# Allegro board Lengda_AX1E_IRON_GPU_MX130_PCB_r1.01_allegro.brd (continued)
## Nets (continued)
GND: C1.2 C2.2 C3.2 C4.2 C5.2 C6.2 C7.2 C8.2 C9.2 C10.2 C11.2 C12.2 C13.2 C14.2 C15.2 C16.2 C17.2 C18.2 C20.1 C21.1 C22.1 C23.1 C24.1 C275.2 C276.2 C298.2 C310.2 C322.2 C326.2 C327.2 C338.2 C342.2 C344.2 C370.2 C471.2 C472.2 C473.2 C474.2 C475.2 C476.2 C536.2 C537.2 C539.2 C540.2 C541.2 C542.2 C543.2 C553.2 C554.2 C555.2 C556.2 C557.2 C558.2 C559.2 C560.2 C561.2 C562.2 C567.2 C568.2 C569.2 C570.2 C571.2 C572.2 C573.2 C574.2 C575.2 C576.2 C577.2 C578.2 C579.2 C580.2 C581.2 C582.2 C583.2 C584.2 C585.2 C586.2 C587.2 C588.2 C596.2 C597.2 C598.2 C599.2 C600.2 C602.2 C603.2 C604.2 C605.2 C606.2 C607.2 C619.2 C620.2 C621.2 C622.2 C623.1 C624.2 C625.2 C628.2 C629.2 C630.1 C631.2 C632.2 C633.2 C634.2 C635.2 C636.2 C637.2 C638.2 C647.2 C670.2 C672.1 C681.2 C682.2 C683.2 C684.2 C691.2 C692.2 C707.2 C710.2 C715.2 C726.2 C729.2 C739.2 C741.2 C742.2 C743.2 C744.2 C745.2 C748.1 C749.2 C758.2 C759.2 C761.2 C764.2 C765.2 C766.2 C769.2 C783.2 C789.2 C804.2 C805.2 C809.2 C810.2 C811.2 C812.2 C813.2 C814.2 C815.2 C816.2 C817.2 C818.2 C819.2 C820.2 C821.2 C822.2 C823.2 C824.2 C825.2 C826.2 C827.2 C828.2 C829.2 C830.2 C831.2 C832.2 C833.2 C834.2 C835.2 C836.2 C837.2 C838.2 C839.2 C840.2 C841.2 C842.2 C843.2 C844.2 C845.2 C846.2 C847.2 C848.2 C849.2 C850.2 C851.2 C852.2 C853.2 C854.2 C855.2 C856.2 C857.2 C858.2 C859.2 C860.2 C861.2 C862.2 C863.2 C864.2 C865.2 C866.2 C867.1 C868.2 C869.2 C870.2 C871.2 C872.2 C873.2 C874.2 C875.2 C876.2 C878.1 C879.1 C881.2 C882.2 C883.2 C884.2 C885.2 C886.2 C887.2 C888.2 C891.2 C896.2 C898.2 C899.2 C900.1 C901.2 C903.2 C904.2 C909.2 C910.1 C911.2 C912.2 C913.1 C914.1 C915.1 C916.1 C917.2 C918.2 C920.2 C921.2 C922.2 C923.2 C924.2 C925.2 C927.2 C928.2 C929.2 C930.2 C931.2 C932.2 C933.2 CP1.2 CP3.2 CP4.2 CP10.2 CP11.2 CP12.2 CP13.2 GC1.2 GC2.1 GC3.1 GC315.1 GC316.2 GC317.1 GCN1.9(GND1) GCN1.15(GND2) GCN1.21(GND3) GCN1.27(GND4) GCN1.29(GND5) GCN1.34(GND10) GCN1.35(GND6) GCN1.40(GND11) GCN1.41(RSVD7) GCN1.47(C_DAT) GCN1.50(GND12) GCN2.E1 GCN2.E2 GCN9.4 GCN9.E1 GCN9.E2 GQ2.2(GND) GR9.2 GR13.2 GU1.22(GND/PWM3) GU1.E1(THERM/GND) M1.A1(VSSQ_1) M1.A3(VSSQ_4) M1.A12(VSSQ_2) M1.A14(VSSQ_3) M1.B5(VSS_2) M1.B10(VSS_1) M1.C1(VSSQ_5) M1.C3(VSSQ_9) M1.C4(VSSQ_10) M1.C11(VSSQ_6) M1.C12(VSSQ_7) M1.C13(EDC1_X16) M1.C14(VSSQ_8) M1.D10(VSS_3) M1.E1(VSSQ_11) M1.E3(VSSQ_14) M1.E12(VSSQ_12) M1.E14(VSSQ_13) M1.F5(VSSQ_16) M1.F10(VSSQ_15) M1.G5(VSS_5) M1.G10(VSS_4) M1.H1(VSS_6) M1.H2(VSSQ_18) M1.H13(VSSQ_17) M1.H14(VSS_7) M1.K1(VSS_8) M1.K2(VSSQ_20) M1.K13(VSSQ_19) M1.K14(VSS_9) M1.L5(VSS_11) M1.L10(VSS_10) M1.M5(VSSQ_22) M1.M10(VSSQ_21) M1.N1(VSSQ_23) M1.N3(VSSQ_26) M1.N12(VSSQ_24) M1.N14(VSSQ_25) M1.P10(VSS_12) M1.R1(VSSQ_27) M1.R3(VSSQ_31) M1.R4(VSSQ_32) M1.R11(VSSQ_28) M1.R12(VSSQ_29) M1.R14(VSSQ_30) M1.T5(VSS_14) M1.T10(VSS_13) M1.V1(VSSQ_33) M1.V3(VSSQ_36) M1.V12(VSSQ_34) M1.V14(VSSQ_35) M2.A1(VSSQ_1) M2.A3(VSSQ_4) M2.A12(VSSQ_2) M2.A14(VSSQ_3) M2.B5(VSS_2) M2.B10(VSS_1) M2.C1(VSSQ_5) M2.C3(VSSQ_9) M2.C4(VSSQ_10) M2.C11(VSSQ_6) M2.C12(VSSQ_7) M2.C13(EDC2_X16) M2.C14(VSSQ_8) M2.D10(VSS_3) M2.E1(VSSQ_11) M2.E3(VSSQ_14) M2.E12(VSSQ_12) M2.E14(VSSQ_13) M2.F5(VSSQ_16) M2.F10(VSSQ_15) M2.G5(VSS_5) M2.G10(VSS_4) M2.H1(VSS_6) M2.H2(VSSQ_18) M2.H13(VSSQ_17) M2.H14(VSS_7) M2.K1(VSS_8) M2.K2(VSSQ_20) M2.K13(VSSQ_19) M2.K14(VSS_9) M2.L5(VSS_11) M2.L10(VSS_10) M2.M5(VSSQ_22) M2.M10(VSSQ_21) M2.N1(VSSQ_23) M2.N3(VSSQ_26) M2.N12(VSSQ_24) M2.N14(VSSQ_25) M2.P10(VSS_12) M2.R1(VSSQ_27) M2.R3(VSSQ_31) M2.R4(VSSQ_32) M2.R11(VSSQ_28) M2.R12(VSSQ_29) M2.R14(VSSQ_30) M2.T5(VSS_14) M2.T10(VSS_13) M2.V1(VSSQ_33) M2.V3(VSSQ_36) M2.V12(VSSQ_34) M2.V14(VSSQ_35) M3.A1(VSSQ_1) M3.A3(VSSQ_4) M3.A12(VSSQ_2) M3.A14(VSSQ_3) M3.B5(VSS_2) M3.B10(VSS_1) M3.C1(VSSQ_5) M3.C3(VSSQ_9) M3.C4(VSSQ_10) M3.C11(VSSQ_6) M3.C12(VSSQ_7) M3.C13(EDC2_X16) M3.C14(VSSQ_8) M3.D10(VSS_3) M3.E1(VSSQ_11) M3.E3(VSSQ_14) M3.E12(VSSQ_12) M3.E14(VSSQ_13) M3.F5(VSSQ_16) M3.F10(VSSQ_15) M3.G5(VSS_5) M3.G10(VSS_4) M3.H1(VSS_6) M3.H2(VSSQ_18) M3.H13(VSSQ_17) M3.H14(VSS_7) M3.K1(VSS_8) M3.K2(VSSQ_20) M3.K13(VSSQ_19) M3.K14(VSS_9) M3.L5(VSS_11) M3.L10(VSS_10) M3.M5(VSSQ_22) M3.M10(VSSQ_21) M3.N1(VSSQ_23) M3.N3(VSSQ_26) M3.N12(VSSQ_24) M3.N14(VSSQ_25) M3.P10(VSS_12) M3.R1(VSSQ_27) M3.R3(VSSQ_31) M3.R4(VSSQ_32) M3.R11(VSSQ_28) M3.R12(VSSQ_29) M3.R14(VSSQ_30) M3.T5(VSS_14) M3.T10(VSS_13) M3.V1(VSSQ_33) M3.V3(VSSQ_36) M3.V12(VSSQ_34) M3.V14(VSSQ_35) M4.A1(VSSQ_1) M4.A3(VSSQ_4) M4.A12(VSSQ_2) M4.A14(VSSQ_3) M4.B5(VSS_2) M4.B10(VSS_1) M4.C1(VSSQ_5) M4.C3(VSSQ_9) M4.C4(VSSQ_10) M4.C11(VSSQ_6) M4.C12(VSSQ_7) M4.C13(EDC1_X16) M4.C14(VSSQ_8) M4.D10(VSS_3) M4.E1(VSSQ_11) M4.E3(VSSQ_14) M4.E12(VSSQ_12) M4.E14(VSSQ_13) M4.F5(VSSQ_16) M4.F10(VSSQ_15) M4.G5(VSS_5) M4.G10(VSS_4) M4.H1(VSS_6) M4.H2(VSSQ_18) M4.H13(VSSQ_17) M4.H14(VSS_7) M4.K1(VSS_8) M4.K2(VSSQ_20) M4.K13(VSSQ_19) M4.K14(VSS_9) M4.L5(VSS_11) M4.L10(VSS_10) M4.M5(VSSQ_22) M4.M10(VSSQ_21) M4.N1(VSSQ_23) M4.N3(VSSQ_26) M4.N12(VSSQ_24) M4.N14(VSSQ_25) M4.P10(VSS_12) M4.R1(VSSQ_27) M4.R3(VSSQ_31) M4.R4(VSSQ_32) M4.R11(VSSQ_28) M4.R12(VSSQ_29) M4.R14(VSSQ_30) M4.T5(VSS_14) M4.T10(VSS_13) M4.V1(VSSQ_33) M4.V3(VSSQ_36) M4.V12(VSSQ_34) M4.V14(VSSQ_35) MH1.1 MH2.1 MH3.1 MH4.1 MH5.1 MH6.1 MH7.1 MH8.1 MH9.1 MH10.1 MH11.1 PCP3.2 Q2.2(S) Q4.2(S) Q7.2(S) Q25.2(S) Q30.2(S) Q38.1(S1) Q38.2(S2) Q38.3(S3) Q39.1(S1) Q39.2(S2) Q39.3(S3) Q41.1(S1) Q41.2(S2) Q41.3(S3) Q42.1(S1) Q42.2(S2) Q42.3(S3) Q54.1(S1) Q54.2(S2) Q54.3(S3) Q55.2(S) Q70.2(S) Q71.2(S) Q72.2(S) Q75.2(S) Q76.2(S) R4.1 R5.1 R7.1 R9.1 R10.1 R15.2 R18.1 R19.1 R23.1 R32.2 R40.2 R44.2 R171.1 R180.1 R181.1 R187.1 R198.1 R240.1 R241.1 R247.1 R248.1 R391.1 R392.2 R528.1 R532.1 R533.1 R556.1 R566.1 R570.1 R587.1 R595.1 R596.1 R597.1 R604.1 R605.2 R606.2 R648.1 R650.2 R659.2 R661.1 R664.2 R665.2 R688.2 R699.2 R703.2 R738.2 R741.2 R744.1 R748.2 R1722.1 U1.1(GND) U2.5(GND) U3.A2(GND_001) U3.A26(GND_002) U3.AA7(GND_F) U3.AB7(GND_H) U3.AB11(GND_003) U3.AB14(GND_004) U3.AB17(GND_005) U3.AB20(GND_006) U3.AB24(GND_007) U3.AC2(GND_008) U3.AC5(GND_011) U3.AC8(GND_012) U3.AC22(GND_009) U3.AC26(GND_010) U3.AD12(GND_013) U3.AD13(GND_014) U3.AD15(GND_015) U3.AD16(GND_016) U3.AD18(GND_017) U3.AD19(GND_018) U3.AD21(GND_019) U3.AD22(GND_020) U3.AE11(GND_021) U3.AE14(GND_022) U3.AE17(GND_023) U3.AE20(GND_024) U3.AF1(GND_025) U3.AF5(GND_031) U3.AF8(GND_032) U3.AF11(GND_026) U3.AF14(GND_027) U3.AF17(GND_028) U3.AF20(GND_029) U3.AF23(GND_030) U3.AG2(GND_033) U3.AG26(GND_034) U3.B1(GND_035) U3.B5(GND_042) U3.B8(GND_043) U3.B11(GND_036) U3.B14(GND_037) U3.B17(GND_038) U3.B20(GND_039) U3.B23(GND_040) U3.B27(GND_041) U3.E2(GND_047) U3.E5(GND_051) U3.E8(GND_052) U3.E11(GND_044) U3.E14(GND_045) U3.E17(GND_046) U3.E20(GND_048) U3.E22(GND_049) U3.E25(GND_050) U3.H23(GND_054) U3.H25(GND_055) U3.K11(GND_057) U3.K13(GND_058) U3.K15(GND_059) U3.K17(GND_060) U3.L5(GND_069) U3.L10(GND_061) U3.L12(GND_062) U3.L14(GND_063) U3.L16(GND_064) U3.L18(GND_065) U3.L23(GND_067) U3.L25(GND_068) U3.M11(GND_070) U3.M13(GND_071) U3.M15(GND_072) U3.M17(GND_073) U3.N10(GND_074) U3.N12(GND_075) U3.N14(GND_076) U3.N16(GND_077) U3.N18(GND_078) U3.P11(GND_079) U3.P13(GND_080) U3.P15(GND_081) U3.P17(GND_082) U3.P23(GND_084) U3.P26(GND_085) U3.R10(GND_087) U3.R12(GND_088) U3.R14(GND_089) U3.R16(GND_090) U3.R18(GND_091) U3.T11(GND_092) U3.T13(GND_093) U3.T15(GND_094) U3.T17(GND_095) U3.U10(GND_096) U3.U12(GND_097) U3.U14(GND_098) U3.U16(GND_099) U3.U18(GND_100) U3.U23(GND_102) U3.U26(GND_103) U3.V11(GND_105) U3.V13(GND_106) U3.V15(GND_107) U3.V17(GND_108) U3.Y2(GND_109) U3.Y5(GND_112) U3.Y23(GND_110) U3.Y26(GND_111) U4.3(GND) U36.4(GND) U37.7(GND) U37.8(PGND) U37.E1 U38.5(GND) U38.E1 U39.5(GND) U39.E1 U40.4(GND1) U40.5(GND2) U40.E1 U41.3(GND) U43.3(GND) U44.3(GND) U46.3(GND) X6.2 X6.4
GNDS_SENSE: U3.F3(GNDS_SENSE)
VDD_GPU: C911.1 R20.2 R704.1 R705.1 R712.2 R739.1 U38.1(VIN1) U38.2(VIN2)
VDD_GPU_AON: C912.1 Q34.1(G) Q35.1(G) Q36.1(G) R37.1 R41.1 R100.1 R251.2 R257.2 R594.1 R599.1 R601.2 R602.1 R614.1 R615.1 R617.1 R619.2 R622.2 R631.2 R634.1 R635.1 R636.1 R637.1 R638.1 R639.1 R640.1 R641.2 R642.1 R643.1 R645.1 R647.1 R704.2 R705.2 R706.1 R750.1 U38.7(VOUT2) U38.8(VOUT1) U39.1(VIN1) U39.2(VIN2)
VDD_GPU_MAIN: C863.1 FB27.2 FB28.1 Q6.1(G) R2.2 R28.2 R154.2 R250.2 R479.2 R480.2 R481.2 R593.1 R598.1 R706.2 R754.1 U36.8(VCC) U39.7(VOUT2) U39.8(VOUT1)
VDDS_SENSE: U3.F4(VDDS_SENSE)
1.5S_LGATE: R701.1 U37.9(DRVL)
1.5S_UGATE: R698.1 U37.13(DRVH)
+VSYS_DCIN: C739.1 C868.1 C869.1 C870.1 C871.1 C872.1 C873.1 C881.1 C882.1 C883.1 C884.1 C885.1 C886.1 C887.1 C896.1 C898.1 CP12.1 GC1.1 GCN1.10(UIM_DATA) GCN1.12(UIM_CLK) GCN1.14(UIM_RESET) GCN1.16(UIM_VPP) GCN2.1 GCN2.2 GCN2.3 GCN2.4 GR1.2 PCP3.1 Q37.5(D1) Q37.6(D2) Q37.7(D3) Q37.8(D4) Q40.5(D1) Q40.6(D2) Q40.7(D3) Q40.8(D4) Q44.5(D1) Q44.6(D2) Q44.7(D3) Q44.8(D4)
CLK_GPU_OE#: GR5.2 Q6.3(D) R153.2
CLK_PCIE_GPU_N: GCN1.11(REFCLK-) U3.AD8(PEX_REFCLK*)
CLK_PCIE_GPU_P: GCN1.13(REFCLK+) U3.AE8(PEX_REFCLK)
EMC_THERM#: R27.1 U2.4(T\H\E\R\M\)
FAN_BACK_GPU: GCN9.2 GD10.P GR428.2 GR429.2
FAN_PWMIN_GPU: GCN1.4(GND7) GCN9.3
FAN_VCC_GPU: GC317.2 GCN9.1 GFB11.1
FB_CAL_PD_VDDQ: R246.2 U3.D22(FB_CAL_PD_VDDQ)
FB_CAL_PU_GND: R247.2 U3.C24(FB_CAL_PU_GND)
FB_CAL_TERM_GND: R248.2 U3.B25(FB_CAL_TERM_GND)
FB_CLAMP: GCN1.3(RSVD1) Q25.3(D) R600.2
FB_PLLAVDD: C567.1 C568.1 C569.1 C570.1 C571.1 FB1.1 FB27.1 U3.F16(FB_PLL_AVDD_1) U3.H22(FB_REFPLL_AVDD) U3.P22(FB_PLL_AVDD_2)
FB_VREF: TP1.1 U3.D23(FB_VREF)
FBA_CLK0: M1.J12(CLK) M3.J12(CLK) R177.2 U3.D24(FBA_CLK0)
FBA_CLK0#: M1.J11(CLK*) M3.J11(CLK*) R176.1 U3.D25(FBA_CLK0*)
FBA_CLK1: M2.J12(CLK) M4.J12(CLK) R14.2 U3.N22(FBA_CLK1)
FBA_CLK1#: M2.J11(CLK*) M4.J11(CLK*) R13.1 U3.M22(FBA_CLK1*)
FBA_CMD0: M1.G12(CS*) M3.L12(CS*) U3.C27(FBA_CMD0)
FBA_CMD1: M1.H10(BA3_A3) M3.K10(BA3_A3) U3.C26(FBA_CMD1)
FBA_CMD2: M1.H11(BA0_A2) M3.K11(BA0_A2) U3.E24(FBA_CMD2)
FBA_CMD3: M1.K11(BA2_A4) M3.H11(BA2_A4) U3.F24(FBA_CMD3)
FBA_CMD4: M1.K10(BA1_A5) M3.H10(BA1_A5) U3.D27(FBA_CMD4)
FBA_CMD5: M1.L12(WE*) M3.G12(WE*) U3.D26(FBA_CMD5)
FBA_CMD6: M1.K4(A8_A7) M3.H4(A8_A7) U3.F25(FBA_CMD6)
FBA_CMD7: M1.K5(A11_A6) M3.H5(A11_A6) U3.F26(FBA_CMD7)
FBA_CMD8: M1.J4(ABI*) M3.J4(ABI*) U3.F23(FBA_CMD8)
FBA_CMD9: M1.J5(A12_RFU) M3.J5(A12_RFU) U3.G22(FBA_CMD9)
FBA_CMD10: M1.H4(A10_A0) M3.K4(A10_A0) U3.G23(FBA_CMD10)
FBA_CMD11: M1.H5(A9_A1) M3.K5(A9_A1) U3.G24(FBA_CMD11)
FBA_CMD12: M1.G3(RAS*) M3.L3(RAS*) U3.F27(FBA_CMD12)
FBA_CMD13: M1.J2(RESET*) M3.J2(RESET*) R240.2 U3.G25(FBA_CMD13)
FBA_CMD14: M1.J3(CKE*) M3.J3(CKE*) R200.1 U3.G27(FBA_CMD14)
FBA_CMD15: M1.L3(CAS*) M3.G3(CAS*) U3.G26(FBA_CMD15)
FBA_CMD16: M2.L12(CS*) M4.G12(CS*) U3.M24(FBA_CMD16)
FBA_CMD17: M2.K10(BA3_A3) M4.H10(BA3_A3) U3.M23(FBA_CMD17)
FBA_CMD18: M2.K11(BA0_A2) M4.H11(BA0_A2) U3.K24(FBA_CMD18)
FBA_CMD19: M2.H11(BA2_A4) M4.K11(BA2_A4) U3.K23(FBA_CMD19)
FBA_CMD20: M2.H10(BA1_A5) M4.K10(BA1_A5) U3.M27(FBA_CMD20)
FBA_CMD21: M2.G12(WE*) M4.L12(WE*) U3.M26(FBA_CMD21)
FBA_CMD22: M2.H4(A8_A7) M4.K4(A8_A7) U3.M25(FBA_CMD22)
FBA_CMD23: M2.H5(A11_A6) M4.K5(A11_A6) U3.K26(FBA_CMD23)
FBA_CMD24: M2.J4(ABI*) M4.J4(ABI*) U3.K22(FBA_CMD24)
FBA_CMD25: M2.J5(A12_RFU) M4.J5(A12_RFU) U3.J23(FBA_CMD25)
FBA_CMD26: M2.K4(A10_A0) M4.H4(A10_A0) U3.J25(FBA_CMD26)
FBA_CMD27: M2.K5(A9_A1) M4.H5(A9_A1) U3.J24(FBA_CMD27)
FBA_CMD28: M2.L3(RAS*) M4.G3(RAS*) U3.K27(FBA_CMD28)
FBA_CMD29: M2.J2(RESET*) M4.J2(RESET*) R241.2 U3.K25(FBA_CMD29)
FBA_CMD30: M2.J3(CKE*) M4.J3(CKE*) R201.1 U3.J27(FBA_CMD30)
FBA_CMD31: M2.G3(CAS*) M4.L3(CAS*) U3.J26(FBA_CMD31)
FBA_D0: M1.A4(DQ0) U3.E18(FBA_D0)
FBA_D1: M1.A2(DQ1) U3.F18(FBA_D1)
FBA_D2: M1.B4(DQ2) U3.E16(FBA_D2)
FBA_D3: M1.B2(DQ3) U3.F17(FBA_D3)
FBA_D4: M1.E4(DQ4) U3.D20(FBA_D4)
FBA_D5: M1.E2(DQ5) U3.D21(FBA_D5)
FBA_D6: M1.F4(DQ6) U3.F20(FBA_D6)
FBA_D7: M1.F2(DQ7) U3.E21(FBA_D7)
FBA_D8: M3.V11(DQ8) U3.E15(FBA_D8)
FBA_D9: M3.V13(DQ9) U3.D15(FBA_D9)
FBA_D10: M3.T11(DQ10) U3.F15(FBA_D10)
FBA_D11: M3.T13(DQ11) U3.F13(FBA_D11)
FBA_D12: M3.N11(DQ12) U3.C13(FBA_D12)
FBA_D13: M3.N13(DQ13) U3.B13(FBA_D13)
FBA_D14: M3.M11(DQ14) U3.E13(FBA_D14)
FBA_D15: M3.M13(DQ15) U3.D13(FBA_D15)
FBA_D16: M1.V11(DQ16) U3.B15(FBA_D16)
FBA_D17: M1.V13(DQ17) U3.C16(FBA_D17)
FBA_D18: M1.T11(DQ18) U3.A13(FBA_D18)
FBA_D19: M1.T13(DQ19) U3.A15(FBA_D19)
FBA_D20: M1.N11(DQ20) U3.B18(FBA_D20)
FBA_D21: M1.N13(DQ21) U3.A18(FBA_D21)
FBA_D22: M1.M11(DQ22) U3.A19(FBA_D22)
FBA_D23: M1.M13(DQ23) U3.C19(FBA_D23)
FBA_D24: M3.A4(DQ24) U3.B24(FBA_D24)
FBA_D25: M3.A2(DQ25) U3.C23(FBA_D25)
FBA_D26: M3.B4(DQ26) U3.A25(FBA_D26)
FBA_D27: M3.B2(DQ27) U3.A24(FBA_D27)
FBA_D28: M3.E4(DQ28) U3.A21(FBA_D28)
FBA_D29: M3.E2(DQ29) U3.B21(FBA_D29)
FBA_D30: M3.F4(DQ30) U3.C20(FBA_D30)
FBA_D31: M3.F2(DQ31) U3.C21(FBA_D31)
FBA_D32: M4.A4(DQ0) U3.R22(FBA_D32)
FBA_D33: M4.A2(DQ1) U3.R24(FBA_D33)
FBA_D34: M4.B4(DQ2) U3.T22(FBA_D34)
FBA_D35: M4.B2(DQ3) U3.R23(FBA_D35)
FBA_D36: M4.E4(DQ4) U3.N25(FBA_D36)
FBA_D37: M4.E2(DQ5) U3.N26(FBA_D37)
FBA_D38: M4.F4(DQ6) U3.N23(FBA_D38)
FBA_D39: M4.F2(DQ7) U3.N24(FBA_D39)
FBA_D40: M2.V11(DQ8) U3.V23(FBA_D40)
FBA_D41: M2.V13(DQ9) U3.V22(FBA_D41)
FBA_D42: M2.T11(DQ10) U3.T23(FBA_D42)
FBA_D43: M2.T13(DQ11) U3.U22(FBA_D43)
FBA_D44: M2.N11(DQ12) U3.Y24(FBA_D44)
FBA_D45: M2.N13(DQ13) U3.AA24(FBA_D45)
FBA_D46: M2.M11(DQ14) U3.Y22(FBA_D46)
FBA_D47: M2.M13(DQ15) U3.AA23(FBA_D47)
FBA_D48: M4.V11(DQ16) U3.AD27(FBA_D48)
FBA_D49: M4.V13(DQ17) U3.AB25(FBA_D49)
FBA_D50: M4.T11(DQ18) U3.AD26(FBA_D50)
FBA_D51: M4.T13(DQ19) U3.AC25(FBA_D51)
FBA_D52: M4.N11(DQ20) U3.AA27(FBA_D52)
FBA_D53: M4.N13(DQ21) U3.AA26(FBA_D53)
FBA_D54: M4.M11(DQ22) U3.W26(FBA_D54)
FBA_D55: M4.M13(DQ23) U3.Y25(FBA_D55)
FBA_D56: M2.A4(DQ24) U3.R26(FBA_D56)
FBA_D57: M2.A2(DQ25) U3.T25(FBA_D57)
FBA_D58: M2.B4(DQ26) U3.N27(FBA_D58)
FBA_D59: M2.B2(DQ27) U3.R27(FBA_D59)
FBA_D60: M2.E4(DQ28) U3.V26(FBA_D60)
FBA_D61: M2.E2(DQ29) U3.V27(FBA_D61)
FBA_D62: M2.F4(DQ30) U3.W27(FBA_D62)
FBA_D63: M2.F2(DQ31) U3.W25(FBA_D63)
FBA_DBI0: M1.D2(DBI0*) U3.D19(FBA_DQM0)
FBA_DBI1: M3.P13(DBI1*) U3.D14(FBA_DQM1)
FBA_DBI2: M1.P13(DBI2*) U3.C17(FBA_DQM2)
FBA_DBI3: M3.D2(DBI3*) U3.C22(FBA_DQM3)
FBA_DBI4: M4.D2(DBI0*) U3.P24(FBA_DQM4)
FBA_DBI5: M2.P13(DBI1*) U3.W24(FBA_DQM5)
FBA_DBI6: M4.P13(DBI2*) U3.AA25(FBA_DQM6)
FBA_DBI7: M2.D2(DBI3*) U3.U25(FBA_DQM7)
FBA_DEBUG0: R194.1 U3.F22(FBA_CMD34)
FBA_DEBUG1: R197.1 U3.J22(FBA_CMD35)
FBA_EDC0: M1.C2(EDC0) U3.E19(FBA_DQS_WP0)
FBA_EDC1: M3.R13(EDC1) U3.C15(FBA_DQS_WP1)
FBA_EDC2: M1.R13(EDC2) U3.B16(FBA_DQS_WP2)
FBA_EDC3: M3.C2(EDC3) U3.B22(FBA_DQS_WP3)
FBA_EDC4: M4.C2(EDC0) U3.R25(FBA_DQS_WP4)
FBA_EDC5: M2.R13(EDC1) U3.W23(FBA_DQS_WP5)
FBA_EDC6: M4.R13(EDC2) U3.AB26(FBA_DQS_WP6)
FBA_EDC7: M2.C2(EDC3) U3.T26(FBA_DQS_WP7)
FBA_VREF_FET_L: Q7.3(D) R179.2
FBA_VREFC: C3.1 C6.1 C9.1 C542.1 M1.J14(VREFC) M2.J14(VREFC) M3.J14(VREFC) M4.J14(VREFC) R178.2 R179.1 R180.2
FBA_WCK01: M1.D4(WCK01) M3.P4(WCK01) U3.D18(FBA_WCK01)
FBA_WCK01#: M1.D5(WCK01*) M3.P5(WCK01*) U3.C18(FBA_WCK01*)
FBA_WCK23: M1.P4(WCK23) M3.D4(WCK23) U3.D17(FBA_WCK23)
FBA_WCK23#: M1.P5(WCK23*) M3.D5(WCK23*) U3.D16(FBA_WCK23*)
FBA_WCK45: M2.P4(WCK01) M4.D4(WCK01) U3.T24(FBA_WCK45)
FBA_WCK45#: M2.P5(WCK01*) M4.D5(WCK01*) U3.U24(FBA_WCK45*)
FBA_WCK67: M2.D4(WCK23) M4.P4(WCK23) U3.V24(FBA_WCK67)
FBA_WCK67#: M2.D5(WCK23*) M4.P5(WCK23*) U3.V25(FBA_WCK67*)
FBVDD: C543.1 C553.1 C554.1 C555.1 C556.1 C557.1 C558.1 C559.1 C560.1 C561.1 C562.1 C572.1 C573.1 C575.1 C576.1 C577.1 C578.1 C579.1 C580.1 C581.1 C582.1 C583.1 C584.1 C585.1 C586.1 C587.1 C588.1 C596.1 C597.1 C598.1 C599.1 C600.1 C602.1 C603.1 C604.1 C605.1 C606.1 C607.1 C619.1 C620.1 C621.1 C622.1 C623.2 C624.1 C625.1 C628.1 C629.1 C630.2 C631.1 C632.1 C633.1 C634.1 C635.1 C636.1 C637.1 C638.1 C647.1 C670.1 C672.2 C681.1 C682.1 C683.1 C684.1 C691.1 C692.1 C707.1 C710.1 C715.1 C726.1 C729.1 C741.1 C742.1 C743.1 C744.1 C745.1 C748.2 C766.1 C769.1 C783.1 C789.1 C811.1 C812.1 C813.1 C814.1 C821.1 C822.1 C823.1 C824.1 C825.1 C826.1 C901.1 C903.1 C904.1 C909.1 CP1.1 CP13.1 L9.2 L10.2 M1.B1(VDDQ_1) M1.B3(VDDQ_4) M1.B12(VDDQ_2) M1.B14(VDDQ_3) M1.C5(VDD_2) M1.C10(VDD_1) M1.D1(VDDQ_5) M1.D3(VDDQ_8) M1.D11(VDD_3) M1.D12(VDDQ_6) M1.D14(VDDQ_7) M1.E5(VDDQ_10) M1.E10(VDDQ_9) M1.F1(VDDQ_11) M1.F3(VDDQ_14) M1.F12(VDDQ_12) M1.F14(VDDQ_13) M1.G1(VDD_4) M1.G2(VDDQ_16) M1.G4(VDD_7) M1.G11(VDD_5) M1.G13(VDDQ_15) M1.G14(VDD_6) M1.H3(VDDQ_18) M1.H12(VDDQ_17) M1.K3(VDDQ_20) M1.K12(VDDQ_19) M1.L1(VDD_8) M1.L2(VDDQ_22) M1.L4(VDD_11) M1.L11(VDD_9) M1.L13(VDDQ_21) M1.L14(VDD_10) M1.M1(VDDQ_23) M1.M3(VDDQ_26) M1.M12(VDDQ_24) M1.M14(VDDQ_25) M1.N5(VDDQ_28) M1.N10(VDDQ_27) M1.P1(VDDQ_29) M1.P3(VDDQ_32) M1.P11(VDD_12) M1.P12(VDDQ_30) M1.P14(VDDQ_31) M1.R5(VDD_14) M1.R10(VDD_13) M1.T1(VDDQ_33) M1.T3(VDDQ_36) M1.T12(VDDQ_34) M1.T14(VDDQ_35) M2.B1(VDDQ_1) M2.B3(VDDQ_4) M2.B12(VDDQ_2) M2.B14(VDDQ_3) M2.C5(VDD_2) M2.C10(VDD_1) M2.D1(VDDQ_5) M2.D3(VDDQ_8) M2.D11(VDD_3) M2.D12(VDDQ_6) M2.D14(VDDQ_7) M2.E5(VDDQ_10) M2.E10(VDDQ_9) M2.F1(VDDQ_11) M2.F3(VDDQ_14) M2.F12(VDDQ_12) M2.F14(VDDQ_13) M2.G1(VDD_4) M2.G2(VDDQ_16) M2.G4(VDD_7) M2.G11(VDD_5) M2.G13(VDDQ_15) M2.G14(VDD_6) M2.H3(VDDQ_18) M2.H12(VDDQ_17) M2.K3(VDDQ_20) M2.K12(VDDQ_19) M2.L1(VDD_8) M2.L2(VDDQ_22) M2.L4(VDD_11) M2.L11(VDD_9) M2.L13(VDDQ_21) M2.L14(VDD_10) M2.M1(VDDQ_23) M2.M3(VDDQ_26) M2.M12(VDDQ_24) M2.M14(VDDQ_25) M2.N5(VDDQ_28) M2.N10(VDDQ_27) M2.P1(VDDQ_29) M2.P3(VDDQ_32) M2.P11(VDD_12) M2.P12(VDDQ_30) M2.P14(VDDQ_31) M2.R5(VDD_14) M2.R10(VDD_13) M2.T1(VDDQ_33) M2.T3(VDDQ_36) M2.T12(VDDQ_34) M2.T14(VDDQ_35) M3.B1(VDDQ_1) M3.B3(VDDQ_4) M3.B12(VDDQ_2) M3.B14(VDDQ_3) M3.C5(VDD_2) M3.C10(VDD_1) M3.D1(VDDQ_5) M3.D3(VDDQ_8) M3.D11(VDD_3) M3.D12(VDDQ_6) M3.D14(VDDQ_7) M3.E5(VDDQ_10) M3.E10(VDDQ_9) M3.F1(VDDQ_11) M3.F3(VDDQ_14) M3.F12(VDDQ_12) M3.F14(VDDQ_13) M3.G1(VDD_4) M3.G2(VDDQ_16) M3.G4(VDD_7) M3.G11(VDD_5) M3.G13(VDDQ_15) M3.G14(VDD_6) M3.H3(VDDQ_18) M3.H12(VDDQ_17) M3.K3(VDDQ_20) M3.K12(VDDQ_19) M3.L1(VDD_8) M3.L2(VDDQ_22) M3.L4(VDD_11) M3.L11(VDD_9) M3.L13(VDDQ_21) M3.L14(VDD_10) M3.M1(VDDQ_23) M3.M3(VDDQ_26) M3.M12(VDDQ_24) M3.M14(VDDQ_25) M3.N5(VDDQ_28) M3.N10(VDDQ_27) M3.P1(VDDQ_29) M3.P3(VDDQ_32) M3.P11(VDD_12) M3.P12(VDDQ_30) M3.P14(VDDQ_31) M3.R5(VDD_14) M3.R10(VDD_13) M3.T1(VDDQ_33) M3.T3(VDDQ_36) M3.T12(VDDQ_34) M3.T14(VDDQ_35) M4.B1(VDDQ_1) M4.B3(VDDQ_4) M4.B12(VDDQ_2) M4.B14(VDDQ_3) M4.C5(VDD_2) M4.C10(VDD_1) M4.D1(VDDQ_5) M4.D3(VDDQ_8) M4.D11(VDD_3) M4.D12(VDDQ_6) M4.D14(VDDQ_7) M4.E5(VDDQ_10) M4.E10(VDDQ_9) M4.F1(VDDQ_11) M4.F3(VDDQ_14) M4.F12(VDDQ_12) M4.F14(VDDQ_13) M4.G1(VDD_4) M4.G2(VDDQ_16) M4.G4(VDD_7) M4.G11(VDD_5) M4.G13(VDDQ_15) M4.G14(VDD_6) M4.H3(VDDQ_18) M4.H12(VDDQ_17) M4.K3(VDDQ_20) M4.K12(VDDQ_19) M4.L1(VDD_8) M4.L2(VDDQ_22) M4.L4(VDD_11) M4.L11(VDD_9) M4.L13(VDDQ_21) M4.L14(VDD_10) M4.M1(VDDQ_23) M4.M3(VDDQ_26) M4.M12(VDDQ_24) M4.M14(VDDQ_25) M4.N5(VDDQ_28) M4.N10(VDDQ_27) M4.P1(VDDQ_29) M4.P3(VDDQ_32) M4.P11(VDD_12) M4.P12(VDDQ_30) M4.P14(VDDQ_31) M4.R5(VDD_14) M4.R10(VDD_13) M4.T1(VDDQ_33) M4.T3(VDDQ_36) M4.T12(VDDQ_34) M4.T14(VDDQ_35) R1.2 R6.2 R178.1 R194.2 R197.2 R200.2 R201.2 R246.1 R702.1 R753.1 U3.B26(FBVDDQ_01) U3.C25(FBVDDQ_02) U3.E23(FBVDDQ_03) U3.E26(FBVDDQ_04) U3.F14(FBVDDQ_05) U3.F21(FBVDDQ_06) U3.G13(FBVDDQ_07) U3.G14(FBVDDQ_08) U3.G15(FBVDDQ_09) U3.G16(FBVDDQ_10) U3.G18(FBVDDQ_11) U3.G19(FBVDDQ_12) U3.G20(FBVDDQ_13) U3.G21(FBVDDQ_14) U3.H24(FBVDDQ_15) U3.H26(FBVDDQ_16) U3.J21(FBVDDQ_17) U3.K21(FBVDDQ_18) U3.L22(FBVDDQ_19) U3.L24(FBVDDQ_20) U3.L26(FBVDDQ_21) U3.M21(FBVDDQ_22) U3.N21(FBVDDQ_23) U3.R21(FBVDDQ_24) U3.T21(FBVDDQ_25) U3.V21(FBVDDQ_26) U3.W21(FBVDDQ_27) U37.3(VOUT)
FRM_CLK: R640.2 U3.A3(GPIO5)
GC6_FB_EN: GR8.2 R603.1 R604.2 U3.B2(GPIO1) U44.2(B)
GPIO0_PWM_VID: R651.1 U3.C6(GPIO0)
GPIO2_GPU_EVENT_FBCLAMP: Q36.2(S) R645.2 U3.D6(GPIO2)
GPIO4_PWR_EN: R637.2 R736.2 R742.2 U3.F9(GPIO4) U41.1(A)
GPIO7_BL_PWM_GPU: R635.2 U3.B6(GPIO7)
GPIO8_MEM_VDD_CTL: R37.2 R39.1 R40.1 R45.2
GPIO8_MEM_VDD_CTL_R: R45.1 U3.E9(GPIO8)
GPIO9_ALERT*: R634.2 U3.F8(GPIO9)
GPIO10_FBVREF_ALTV: Q7.1(G) R198.2 R638.2 U3.C5(GPIO10)
GPIO12_AC_DETECT_GPU: D9.P R642.2 U3.D7(GPIO12)
GPIO13_BLEN_GPU: R636.2 U3.B4(GPIO13)
GPIO16_GPU_PEX_RST_MON: R34.1 R639.2 U3.D5(GPIO16)
GPIO17_MULTIPLE_USAGE: R36.1 U3.D4(GPIO17)
GPIO18_GM108_PEXRSTHOLD: R35.1 U3.C2(GPIO18)
GPIO21_GPU_PEX_RST_HOLD: R33.1 U3.C4(GPIO21)
GPIO22_MEM_VDD_CTL2: R36.2 R41.2 R43.1 R44.1 U3.A7(GPIO22)
GPIO23_GPU_PEX_RST_HOLD: R35.2 R643.2 U3.B7(GPIO23)
GPIO_NVVDD_PSI: R649.1 U3.A4(GPIO6)
GPU_ADP_IN#: D9.N GCN1.20(W_DISABLE#)
GPU_ALL_PWRGD_SOC: C933.1 GCN1.5(RSVD2) R757.2
GPU_BUFRST*: R587.2 U3.D11(BUFRST*)
GPU_EVENT: GCN1.28(+1.5V_2) Q36.3(D) R644.2
GPU_PEX_RST#: GCN1.22(PERST#) R30.2 R31.1 U4.1(A)
GPU_PEX_RST_HOLD: R33.2 U4.2(B)
GPU_PLLVDD: C860.1 C861.1 FB2.2 FB28.2 R252.1 R259.1 R482.1
GPU_PWR_EN: GR11.2 Q76.1(G) R737.2 R738.1 U43.2(B)
I2C_CLK2_GPU: GCN1.30(SMB_CLK) Q34.3(D) U2.8(SMCLK)
I2C_DATA2_GPU: GCN1.32(SMB_DATA) Q35.3(D) U2.7(SMDATA)
I2CB_SCL_G: R631.1 U3.C9(I2CB_SCL)
I2CB_SDA_G: R641.1 U3.C8(I2CB_SDA)
I2CC_SCL_G: R619.1 U3.A9(I2CC_SCL)
I2CC_SDA_G: R622.1 U3.B9(I2CC_SDA)
I2CS_SCL_G: Q34.2(S) R614.2 U3.D9(I2CS_SCL)
I2CS_SDA_G: Q35.2(S) R615.2 U3.D8(I2CS_SDA)
IFP_IOVDD_1: U3.W6(IFP_IOVDD_1)
IFP_IOVDD_2: U3.Y6(IFP_IOVDD_2)
IFPAB_PLLVDD: U3.W7(IFPAB_PLLVDD)
JTAG_TCLK: TP9.1 U3.AE5(JTAG_TCK)
JTAG_TDI: TP19.1 U3.AF6(JTAG_TDO)
JTAG_TDO: TP24.1 U3.AD6(JTAG_TMS)
JTAG_TMS: TP15.1 U3.AE6(JTAG_TDI)
JTAG_TRST*: R605.1 TP26.1 U3.AG4(JTAG_TRST*)
KBC_FAN_SPEED_GPU: GC315.2 GCN1.6(+1.5V_1) GQ2.3(OUT) GR427.2
NVVDD: C749.1 C758.1 C759.1 C761.1 C764.1 C765.1 C804.1 C805.1 C809.1 C810.1 C815.1 C816.1 C817.1 C818.1 C819.1 C820.1 C827.1 C828.1 C829.1 C830.1 C831.1 C832.1 C833.1 C834.1 C835.1 C836.1 C837.1 C838.1 C839.1 C840.1 C841.1 C842.1 C843.1 C844.1 C845.1 C846.1 C847.1 C848.1 C853.1 C854.1 C876.1 CP3.1 CP4.1 CP10.1 CP11.1 L1.2 L8.2 R677.2 R751.1 U3.G1(XVDD_1) U3.G2(XVDD_2) U3.G3(XVDD_3) U3.G4(XVDD_4) U3.G5(XVDD_5) U3.G6(XVDD_6) U3.G7(XVDD_7) U3.H3(XVDD_8) U3.H4(XVDD_9) U3.H6(XVDD_10) U3.J1(XVDD_11) U3.J2(XVDD_12) U3.J3(XVDD_13) U3.J4(XVDD_14) U3.J5(XVDD_15) U3.J6(XVDD_16) U3.J7(XVDD_17) U3.K1(XVDD_18) U3.K2(XVDD_19) U3.K3(XVDD_20) U3.K4(XVDD_21) U3.K5(XVDD_22) U3.K6(XVDD_23) U3.K7(XVDD_24) U3.K10(VDD_001) U3.K12(VDD_002) U3.K14(VDD_003) U3.K16(VDD_004) U3.K18(VDD_005) U3.L3(XVDD_25) U3.L4(XVDD_26) U3.L11(VDDS_1) U3.L13(VDD_006) U3.L15(VDD_007) U3.L17(VDDS_2) U3.M1(XVDD_27) U3.M2(XVDD_28) U3.M3(XVDD_29) U3.M4(XVDD_30) U3.M5(XVDD_31) U3.M7(XVDD_32) U3.M10(VDD_008) U3.M12(VDD_009) U3.M14(VDDS_3) U3.M16(VDD_010) U3.M18(VDD_011) U3.N1(XVDD_33) U3.N2(XVDD_34) U3.N3(XVDD_35) U3.N4(XVDD_36) U3.N5(XVDD_37) U3.N7(XVDD_38) U3.N11(VDD_012) U3.N13(VDD_013) U3.N15(VDD_014) U3.N17(VDD_015) U3.P3(XVDD_39) U3.P4(XVDD_40) U3.P6(XVDD_41) U3.P10(VDDS_4) U3.P12(VDDS_5) U3.P14(VDD_016) U3.P16(VDDS_6) U3.P18(VDDS_7) U3.R1(XVDD_42) U3.R2(XVDD_43) U3.R3(XVDD_44) U3.R4(XVDD_45) U3.R5(XVDD_46) U3.R6(XVDD_47) U3.R7(XVDD_48) U3.R11(VDD_017) U3.R13(VDD_018) U3.R15(VDD_019) U3.R17(VDD_020) U3.T1(XVDD_49) U3.T2(XVDD_50) U3.T3(XVDD_51) U3.T4(XVDD_52) U3.T5(XVDD_53) U3.T6(XVDD_54) U3.T7(XVDD_55) U3.T10(VDD_021) U3.T12(VDD_022) U3.T14(VDDS_8) U3.T16(VDD_023) U3.T18(VDD_024) U3.U3(XVDD_56) U3.U4(XVDD_57) U3.U6(XVDD_58) U3.U11(VDDS_9) U3.U13(VDD_025) U3.U15(VDD_026) U3.U17(VDDS_10) U3.V1(XVDD_59) U3.V2(XVDD_60) U3.V3(XVDD_61) U3.V4(XVDD_62) U3.V5(XVDD_63) U3.V6(XVDD_64) U3.V10(VDD_027) U3.V12(VDD_028) U3.V14(VDD_029) U3.V16(VDD_030) U3.V18(VDD_031) U3.W1(XVDD_66) U3.W2(XVDD_67) U3.W3(XVDD_68) U3.W4(XVDD_69)
NVVDD_GND_SENSE: C890.2 C893.1 GU1.10(RGND) R658.2 R665.1 U3.F1(GND_SENSE)
NVVDD_SENSE: C892.2 C893.2 R676.2 R677.1 U3.F2(VDD_SENSE)
OVERT: GCN1.46(LED_WPAN#) Q33.3(D)
OVERT1: C867.2 Q33.2(S) R618.1
PCIE_RXN1_GPU: C331.1 GCN1.44(LED_WLAN#)
PCIE_RXN2_GPU: C333.1 GCN1.38(USB_D+)
PCIE_RXN3_GPU: C532.1 GCN1.51(RSVD12)
PCIE_RXN4_GPU: C534.1 GCN1.45(C_CLK)
PCIE_RXP1_GPU: C330.1 GCN1.42(LED_WWAN#)
PCIE_RXP2_GPU: C332.1 GCN1.36(USB_D-)
PCIE_RXP3_GPU: C478.1 GCN1.49(C_RST)
PCIE_RXP4_GPU: C533.1 GCN1.43(RSVD8)
PCIE_TXN1_GPU: GCN1.39(RSVD6) U3.AG7(PEX_RX0*)
PCIE_TXN2_GPU: GCN1.33(PET_P0) U3.AE7(PEX_RX1*)
PCIE_TXN3_GPU: GCN1.25(PER_P0) U3.AF9(PEX_RX2*)
PCIE_TXN4_GPU: GCN1.19(RSVD4) U3.AG10(PEX_RX3*)
PCIE_TXP1_GPU: GCN1.37(RSVD5) U3.AG6(PEX_RX0)
PCIE_TXP2_GPU: GCN1.31(PET_N0) U3.AF7(PEX_RX1)
PCIE_TXP3_GPU: GCN1.23(PER_N0) U3.AE9(PEX_RX2)
PCIE_TXP4_GPU: GCN1.17(RSVD3) U3.AG9(PEX_RX3)
PEX_CLKREQ_GPU#: Q6.2(S) R100.2 R153.1 U3.AC6(PEX_CLKREQ*)
PEX_PLL_CLK_OUT: R12.1 U3.AF22(NC_11)
PEX_PLL_HVDD: C536.1 C537.1 R8.1 R154.1 U3.AA8(PEX_PLL_HVDD_1) U3.AA9(PEX_PLL_HVDD_2)
PEX_RST#: Q33.1(G) R31.2 R32.1 U3.AC7(PEX_RST*) U4.4(Y)
PEX_SVDD_3V3: R8.2 U3.AB8(NC_4)
PEX_TERMP: R171.2 U3.AF25(PEX_TERMP)
PEX_TX0: C330.2 U3.AC9(PEX_TX0)
PEX_TX0#: C331.2 U3.AB9(PEX_TX0*)
PEX_TX1: C332.2 U3.AB10(PEX_TX1)
PEX_TX1#: C333.2 U3.AC10(PEX_TX1*)
PEX_TX2: C478.2 U3.AD11(PEX_TX2)
PEX_TX2#: C532.2 U3.AC11(PEX_TX2*)
PEX_TX3: C533.2 U3.AC12(PEX_TX3)
PEX_TX3#: C534.2 U3.AB12(PEX_TX3*)
PEX_VDD: C11.1 C14.1 C275.1 C276.1 C298.1 C310.1 C322.1 C326.1 C327.1 C923.1 C924.1 C925.1 C926.1 FB1.2 FB2.1 L11.2 R3.2 R11.1 R746.1 R752.1 U3.AA22(PEX_DVDD_1) U3.AB23(PEX_DVDD_2) U3.AC24(PEX_DVDD_3) U3.AD25(PEX_DVDD_4) U3.AE26(PEX_DVDD_5) U3.AE27(PEX_DVDD_6)
PS1_NVVDD_BOOT1: GU1.1(BOOT1) R646.2
PS1_NVVDD_BOOT1_RC: C877.1 R646.1
PS1_NVVDD_BOOT2: GU1.18(BOOT2) R652.2
PS1_NVVDD_BOOT2_RC: C880.1 R652.1
PS1_NVVDD_EN: C878.2 GU1.3(EN) R743.2 R744.2
PS1_NVVDD_FB: GU1.11(VSNS) R666.1 R670.1
PS1_NVVDD_FB_RC: C892.1 R666.2
PS1_NVVDD_LG1: GU1.23(LGATE1) Q38.4(G) Q39.4(G) R650.1
PS1_NVVDD_LG2: GU1.20(LGATE2) Q41.4(G) Q42.4(G) R659.1
PS1_NVVDD_PGOOD: GU1.16(PGOOD) R749.2 R756.1 U41.2(B) U44.1(A)
PS1_NVVDD_PH1_Q: C877.2 GU1.24(PHASE1) L1.1 Q37.1(S1) Q37.2(S2) Q37.3(S3) Q38.5(D1) Q38.6(D2) Q38.7(D3) Q38.8(D4) Q39.5(D1) Q39.6(D2) Q39.7(D3) Q39.8(D4)
PS1_NVVDD_PH2_Q: C880.2 C889.1 GU1.19(PHASE2) L8.1 Q40.1(S1) Q40.2(S2) Q40.3(S3) Q41.5(D1) Q41.6(D2) Q41.7(D3) Q41.8(D4) Q42.5(D1) Q42.6(D2) Q42.7(D3) Q42.8(D4)
PS1_NVVDD_PSI: GU1.4(PSI) R647.2 R648.2 R649.2
PS1_NVVDD_REFADJ: GU1.6(REFADJ) R656.1
PS1_NVVDD_REFIN: GU1.7(REFIN) R654.2 R657.1
PS1_NVVDD_SENSE_R: R670.2 R676.1
PS1_NVVDD_UG1: GU1.2(UGATE1) Q37.4(G)
PS1_NVVDD_UG2: GU1.17(UGATE2) Q40.4(G)
PS1_NVVDD_VREF: C879.2 GR6.1 GU1.8(VREF) R655.1
PS2_FBVDD_PGOOD: R700.1 U46.2(B)
PS2_FBVDDQ_EN: R687.1 R756.2 U44.4(Y)
PS5_1V05_PGOOD: R740.2 U40.9(POK) U46.1(A)
PS5_1V05_SNUB: C919.2 R741.1
PS5_PEXVDD_EN: R745.1 U43.4(Y)
PS_FBVDD_SEL: C22.2 Q4.1(G) R39.2
PS_FBVDD_SEL2: C23.2 Q2.1(G) R43.2
PS_FBVDD_SEL2_Q: Q2.3(D) R42.1
PS_FBVDD_SEL_Q: Q4.3(D) R38.1
ROM_CS*: R483.1 U3.D12(ROM_CS*)
ROM_CS_R*: R480.1 R483.2 U36.1(CS#)
ROM_SCLK: R517.1 R592.1 R597.2 U3.C12(ROM_SCLK)
ROM_SCLK_R: R517.2 U36.6(SCLK)
ROM_SI: R516.1 R588.1 R595.2 U3.B12(ROM_SI)
ROM_SI_R: R516.2 U36.5(SI/SIO0)
ROM_SO: R589.1 R596.2 U3.A12(ROM_SO) U36.2(SO/SIO1)
SP_PLLVDD: C574.1 C858.1 C859.1 R252.2 U3.L6(XS_PLLVDD) U3.M6(SP_PLLVDD)
STRAP0: R485.1 R528.2 U3.D1(STRAP0)
STRAP1: R486.1 R532.2 U3.D2(STRAP1)
STRAP2: R505.1 R533.2 U3.E4(STRAP2)
STRAP3: R507.1 R556.2 U3.E3(STRAP3)
STRAP4: R514.1 R566.2 U3.D3(STRAP4)
STRAP5: R515.1 R570.2 U3.C1(STRAP5)
STRAP_VDD0: R485.2 R486.2 R505.2 R507.2 R514.2 R515.2 R598.2 R599.2
STRAP_VDD1: R588.2 R589.2 R592.2 R593.2 R594.2
SYS_PEX_RST_MON#: R30.1 R34.2
VID_PLLVDD: C866.1 R482.2 U3.N6(VID_PLLVDD)
XTAL_SSFOUT: R28.1 R29.2 R391.2 U3.A10(XTAL_SSIN)
XTALIN: C864.1 U3.C11(XTAL_IN) X6.1
XTALOUT: C865.1 U3.B10(XTAL_OUT) X6.3
XTALOUTB: R257.1 R392.1 U3.C10(XTAL_OUTBUFF)
XVDD_65: U3.V7(XVDD_65)
N37829238: C338.1 C342.1 C344.1 C370.1 C471.1 C472.1 C473.1 C474.1 C475.1 C476.1 R2.1 R3.1 U3.AA10(PEX_HVDD_1) U3.AA12(PEX_HVDD_2) U3.AA13(PEX_HVDD_3) U3.AA16(PEX_HVDD_4) U3.AA18(PEX_HVDD_5) U3.AA19(PEX_HVDD_6) U3.AA20(PEX_HVDD_7) U3.AA21(PEX_HVDD_8) U3.AB22(PEX_HVDD_9) U3.AC23(PEX_HVDD_10) U3.AD24(PEX_HVDD_11) U3.AE25(PEX_HVDD_12) U3.AF26(PEX_HVDD_13) U3.AF27(PEX_HVDD_14)
N37838176: C541.1 R176.2 R177.1
N37838335: M1.J10(SEN) R187.2
N37838338: M1.J1(MF_VSS) R1722.2
N37838367: C539.1 M1.A10(VREFD_L)
N37838374: C540.1 M1.V10(VREFD_H)
N37838412: M1.J13(ZQ) R181.2
N37848751: C855.1 C856.1 C857.1 R251.1 U3.G10(1V8_AON_1) U3.G12(1V8_AON_2)
N37848802: C849.1 C850.1 C851.1 C852.1 R250.1 U3.G8(VDD18_1) U3.G9(VDD18_2)
N37855686: C862.1 R259.2 U3.F11(GPCPLL_AVDD)
N37857234: R479.1 U36.3(WP#/ACC)
N37857254: R481.1 U36.7(HOLD#)
N37859198: R617.2 R618.2 U3.A6(OVERT)
N37859508: Q30.1(G) R602.2 R603.2
N37859577: R606.1 U3.AD9(NVJTAG_SEL)
N37859659: Q25.1(G) Q30.3(D) R601.1
N37865747: C899.1 R679.2 R687.2 R688.1 U37.1(EN_PSV)
N37866050: Q54.4(G) R701.2
N37866054: C894.1 L9.1 L10.1 Q44.1(S1) Q44.2(S2) Q44.3(S3) Q54.5(D1) Q54.6(D2) Q54.7(D3) Q54.8(D4) R695.2 U37.12(LL)
N37866151: Q44.4(G) R698.2
N37866161: R38.2 R42.2 R702.2 R703.1 U37.5(VFB)
N37866183: R691.1 U37.14(VBST)
N37866191: C894.2 D12.N R691.2
N37866234: R697.2 R700.2 U37.6(PGOOD)
N37866247: C910.2 R696.1 U37.4(V5FILT)
N37866267: R695.1 U37.2(TON)
N37866286: R699.1 U37.11(TRIP)
N37869610: R739.2 R742.1 R743.1
N37869740: C931.1 Q55.1(G) Q70.1(G) Q71.1(G) Q72.1(G) Q75.1(G) Q76.3(D) R755.1
N37869742: Q55.3(D) R750.2
N37869760: Q70.3(D) R751.2
N37869825: C918.1 R736.1 U39.3(ON)
N37869827: Q71.3(D) R752.2
N37869857: C914.2 U39.6(CT)
N37869898: U41.4(Y) U43.1(A)
N37869909: Q75.3(D) R754.2
N37869942: Q72.3(D) R753.2
N37869983: C913.2 U38.6(CT)
N37870019: C922.1 R745.2 U40.10(EN)
N37870106: C919.1 L11.1 U40.6(SW1) U40.7(SW2)
N37870110: C926.2 R746.2 R748.1 U40.1(FB)
N37870179: R757.1 U46.4(Y)
N37870204: C917.1 R734.2 R737.1 U38.3(ON)
N37870231: C929.1 R747.2 U40.2(VCC)
N377081311: GD10.N GQ2.1(IN)
N377081313: GC316.1 GR429.1
N377124615: GCN1.48(+1.5V_3) GR13.1
N377124828: GCN1.2(+3.3V_1) GR2.2
N377124914: GCN1.18(GND8) GR8.1
N377124971: GCN1.7(CLKREQ#) GR5.1
N377125005: GCN1.26(GND9) GR11.1
N377128729: C1.1 M2.V10(VREFD_L)
N377128738: M2.J10(SEN) R5.2
N377128750: M2.J13(ZQ) R4.2
N377128755: M2.J1(MF_VDD) R1.1
N377131759: C4.1 M3.V10(VREFD_L)
N377131768: M3.J10(SEN) R10.2
N377131780: M3.J13(ZQ) R9.2
N377131785: M3.J1(MF_VDD) R6.1
N377139840: C8.1 R13.2 R14.1
N377139974: M4.J10(SEN) R19.2
N377139977: M4.J1(MF_VSS) R7.2
N377139998: C5.1 M4.A10(VREFD_L)
N377140043: M4.J13(ZQ) R18.2
N377218676: C2.1 C7.1 C10.1 R11.2 U3.AA14(NC_1) U3.AA15(NC_2)
N377219078: R12.2 U3.AE22(NC_7)
N377219165: R15.1 U3.F6(NC_19)
N377220187: R21.1 R23.2 U1.2(FB)
N377220203: C16.1 R22.1 U1.5(VIN1) U1.E1(VIN2)
N377220223: R17.1 U1.8(EN)
N377220249: R16.2 U1.7(POK)
N377223530: Q1.1(B) Q1.3(C) R24.2
N377223586: C19.2 R25.1 U2.3(DN)
N377223596: Q1.2(E) R25.2
N377223598: C19.1 R24.1 U2.2(DP)
N377223616: R26.2 U2.6(A\L\E\R\T\)
N377254854: GC2.2 GR1.1 GU1.9(TON)
N377255891: C888.1 GU1.5(VID) R651.2
N377256292: C890.1 R654.1 R655.2 R656.2
N377256298: R657.2 R658.1
N377257492: C891.1 GU1.12(SS) R664.1
N377258862: C889.2 R661.2
N377263043: GC3.2 GR3.2 GU1.15(VCC/ISEN1)
N377264652: GR4.2 GU1.14(TALERT/ISEN2)
N377264674: GR6.2 GR9.1 GU1.13(TSNS/ISEN3)
N377286625: C20.2 R29.1
N377300898: C24.2 U3.AE2(TS_VREF)

Pads without a net: GCN1 1; M1 A5 A11 A13 B11 B13 D13 E11 E13 F11 F13 M2 M4 N2 N4 P2 R2 T2 T4 V2 V4 V5; M2 A5 A10 A11 A13 B11 B13 D13 E11 E13 F11 F13 M2 M4 N2 N4 P2 R2 T2 T4 V2 V4 V5; M3 A5 A10 A11 A13 B11 B13 D13 E11 E13 F11 F13 M2 M4 N2 N4 P2 R2 T2 T4 V2 V4 V5; M4 A5 A11 A13 B11 B13 D13 E11 E13 F11 F13 M2 M4 N2 N4 P2 R2 T2 T4 V2 V4 V5 V10; MARK1 1; MARK2 1; MARK3 1; MARK4 1; MARK5 1; MARK6 1; MARK7 1; MARK8 1; U3 A16 A22 AA1 AA2 AA3 AA4 AA5 AA6 AB1 AB2 AB3 AB4 AB5 AB6 AB13 AB15 AB16 AB18 AB19 AB21 AB27 AC3 AC4 AC13 AC14 AC15 AC16 AC17 AC18 AC19 AC20 AC21 AD1 AD2 AD3 AD4 AD5 AD7 AD10 AD14 AD17 AD20 AD23 AE1 AE3 AE4 AE10 AE12 AE13 AE15 AE16 AE18 AE19 AE21 AE23 AE24 AF2 AF3 AF4 AF10 AF12 AF13 AF15 AF16 AF18 AF19 AF21 AF24 AG3 AG12 AG13 AG15 AG16 AG18 AG19 AG21 AG22 AG24 AG25 B3 B19 C3 C7 C14 D10 E6 E7 E10 E12 F5 F7 F10 F12 F19 H2 H5 L2 P2 P5 P25 T27 U2 U5 W5 W22 Y3 Y4; U40 8

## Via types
v1: diameter 0.45, hole 0.25, TOP to BOTTOM, 1320 vias
v2: diameter 0.7, hole 0.4, TOP to BOTTOM, 227 vias
v3: diameter 0.48, hole 0.28, TOP to BOTTOM, 41 vias

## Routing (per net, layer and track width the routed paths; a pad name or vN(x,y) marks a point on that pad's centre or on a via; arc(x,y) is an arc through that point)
5V_SW: length 238.1
  TOP w0.305: U40.3 69.28,75.49 C920.1 ; R755.2 71.75,75.89 R747.1 71.13,78.09 70.79,78.43 R735.2
  TOP w0.508: C920.1 69.27,76.69 C921.1 69.27,76.98 70.33,78.05 R735.2
  TOP w1.016: R735.2 v2(70.33,79.25)
  L3 w0.305: 64.91,61.77 65.43,62.29 ; 65.43,62.29 64.91,62.81 ; 65.43,62.29 v1(68.8,62.29)
  L3 w0.406: v2(70.33,79.25) 72.15,79.25 72.96,78.44 72.96,77.72 71.91,76.66 71.91,73.22 69.16,70.48 69.16,69.13 69.79,68.51 71.74,68.51 72.9,67.35 72.9,65.73 71.11,63.94 71.11,62.21 72.57,60.75 72.57,45.67 67.07,40.18 67.07,35.53 65.28,33.74 v1(65.28,33.33) 65.28,28.42 66.81,26.88 66.81,23.75 65.22,22.16 65.22,17.51 64.39,16.68 64.39,11.14 61.98,8.73 44.72,8.73 44.4,9.05 37.64,9.05 37.03,9.66 33.29,9.66 32.37,8.74 25.37,8.74 20.5,13.62 20.5,19.37 17.65,22.22 v1(17.65,28.14)
  L3 w0.508: v2(70.33,79.25) 69.52,78.44 69.52,74.91 67.22,72.61 67.22,65.47 64.91,63.16 64.91,61.55 62.9,59.54 62.9,52.06 v1(62.09,51.25) 59.61,48.77 59.61,47.49 60.68,46.42 60.68,37.99 v1(59.66,36.98)
  L6 w0.305: v1(12.01,37.08) 11.66,36.72 11.66,30.19 v1(12,29.85)
  BOTTOM w0.305: GU1.21 60.79,38.11 60.22,38.68 C874.1 59.22,38.49 C875.1 59.22,37.42 v1(59.66,36.98) ; U39.4 62.16,52.39 C915.2 61.54,51.46 61.75,51.25 v1(62.09,51.25) ; v1(68.8,62.29) C916.2 68.2,62.41 U38.4 ; C900.2 11.98,37.11 v1(12.01,37.08) 12.01,37.06 12.49,36.59 U37.10
  BOTTOM w0.406: v1(12,29.85) 11.98,29.84 R696.2 11.98,28.88 12.73,28.14 v1(17.65,28.14) 19.3,29.78 19.3,31.44 ; 19.3,32.03 19.3,31.73 ; 19.3,32.03 18.99,31.73 ; 19.3,32.03 D12.P ; 19.3,31.73 19.01,31.73 ; 19.3,31.73 19.3,31.44 ; GR4.1 v1(65.28,33.33) ; 19.3,31.44 19.01,31.73 ; 19.01,31.73 18.99,31.73 ; 18.99,31.73 R679.1
+V1P8S: length 2
  TOP w0.305: 69.68,81.42 69.68,81.42 70.04,81.78 ; 69.68,81.42 69.39,81.7 ; 69.68,81.42 69.68,81.95 ; 69.68,81.42 R21.2
  vias: v2(72.75,82.26) v2(73.52,82.24)
+V3.3S: length 313.7
  TOP w0.203: R26.1 22.17,24.32 v1(22.05,24.2) ; R740.1 69.78,68.11 70.02,67.87 v1(70.03,67.87)
  TOP w0.305: 70.77,92.14 70.77,91.6 ; 70.77,92.14 71.03,91.88 ; 70.77,92.14 71.24,92.14 ; 70.77,92.14 70.38,92.53 68.47,92.53 67.72,91.78 R16.1 R17.2 ; U2.1 29.51,23.64 29.78,23.38 C18.1 v1(30.39,22.82) ; R27.2 v1(31.92,25.96)
  TOP w0.508: v2(47.18,7.85) 47.18,5.96 47.65,5.49 GCN1.24
  TOP w0.635: GCN1.52 36.45,3.24 34.62,5.07 v2(34.62,8.67)
  L3 w0.305: v1(22.05,24.2) 22.53,23.72 v1(22.53,20.22)
  L3 w0.762: v2(47.18,7.85) 44.11,7.85 43.63,8.34 37.1,8.34 36.51,8.92 34.87,8.92 v2(34.62,8.67)
  L6 w0.305: 74.46,67.4 74.45,67.4 ; 74.46,67.4 75.03,66.83 ; 74.46,67.4 75.02,67.4 75.03,67.39 ; 74.45,67.4 70.47,67.4 70.03,67.85 v1(70.03,67.87) ; 74.45,67.4 75.03,67.99 ; v1(13.54,70.31) 13.57,70.31 14.38,69.5 14.38,31.68 13.34,30.64 13.34,29.96 13.86,29.44 13.86,26.94 13.22,26.31 13.22,23.2 14.15,22.27 14.15,10.52 15.72,8.95 17.23,8.95 18.21,9.92 25.41,9.92 v1(28.49,13) 31.31,13 34.62,9.68 v2(34.62,8.67)
  L6 w1.016: 75.03,67.99 75.03,62.05 72.89,59.9 72.89,46.14 71.25,44.51 71.25,40.21 72.89,38.58 72.89,22.6 69.05,18.76 54.94,18.76 47.18,11 v2(47.18,7.85)
  BOTTOM w0.305: C930.1 27.86,12.17 R749.1 ; C930.1 27.72,12.86 U44.5 ; C930.1 v1(28.49,13) 28.68,13 29.01,13.33 29.01,15.3 28.5,15.8 28.5,16.86 28.92,17.28 28.92,18.62 ; R697.1 8.51,33.51 8.2,33.2 8.2,24.9 8.68,24.42 U46.5 C932.1 9.79,22.54 9.79,21.33 11.24,19.88 11.24,14.22 12.84,12.62 12.84,11.04 15.71,8.17 20.12,8.17 20.89,8.95 ; v1(22.53,20.22) 22.53,20.22 R644.1 22.53,19.06 22.69,18.9 ; R734.1 68.95,65.05 69.76,65.86 69.76,67.61 v1(70.03,67.87) ; 22.69,18.9 25.7,18.9 26.68,19.88 R600.1 27.68,19.42 28.23,18.87 28.68,18.87 ; 22.69,18.9 C927.1 ; U41.5 C927.1 ; C927.1 22.19,16.94 21.74,16.49 C928.1 21.74,14.95 22.06,14.63 U43.5 21.43,14.16 20.89,13.62 20.89,9.25 ; 28.92,18.62 28.92,18.87 ; 28.92,18.62 28.68,18.87 ; 28.92,18.87 28.68,18.87 ; 28.92,18.87 30.39,20.34 v1(30.39,22.82) 31.92,24.35 v1(31.92,25.96) ; 20.89,8.95 21.2,8.95 ; 20.89,8.95 20.89,9.25 ; U4.5 C21.2 33.75,11.66 33.53,11.44 32.18,11.44 28.96,8.21 21.93,8.21 21.2,8.95 ; 21.2,8.95 20.89,9.25 ; GR427.1 v1(13.54,70.31)
  vias: v2(71.59,91.5) v2(72.34,91.5)
+V5S: length 268.2
  TOP w0.305: U1.6 C17.1
  TOP w0.4: C17.1 v1(69.8,89.95)
  TOP w0.508: GCN1.8 57.25,3.86 v2(58.45,5.06)
  L3 w0.406: v1(66.05,32.12) 66.48,32.12 67.07,31.54 67.07,27.79 67.97,26.89 67.97,23.82 67.08,22.93 67.08,18.47 65.14,16.53 65.14,11.08 v1(64.38,10.32) 61.62,7.56 v1(60.53,7.56) ; v2(68.83,79.31) 68.11,80.03 68.11,88.26 v1(69.8,89.95) ; v1(11.8,74.75) 11.81,74.73 11.81,68.47 13.66,66.62 13.66,37.81 11.22,35.37 11.22,31.72 8.59,29.09 8.59,26.68 14.25,21.02 14.25,14.03 13.63,13.4 13.63,10 17.79,5.83 40.11,5.83 40.91,5.03 47.98,5.03 49.38,6.43 56.59,6.43 57.96,5.06 v2(58.45,5.06)
  L3 w1.016: v2(58.45,5.06) v2(59.21,5.06) 59.37,4.9 63.63,4.9 v2(65.44,6.7) 71.58,12.85 71.58,17.2 73.77,19.4 73.77,41.53 75.01,42.77 75.01,73.28 73.88,74.41 73.88,80.31 73.05,81.13 70.66,81.13 v2(68.83,79.31)
  L6 w0.406: v2(58.45,5.06) 58.45,5.48 v1(60.53,7.56)
  BOTTOM w0.305: GR3.1 65.83,31.9 v1(66.05,32.12)
  BOTTOM w0.406: GR428.1 11.13,76.1 GFB11.2 11.81,74.76 v1(11.8,74.75) ; GR2.1 v1(64.38,10.32)
  BOTTOM w0.762: v2(65.44,6.7) 65.44,8.9 64.99,9.35 GR2.1
GND: length 544
  TOP w0.15: v1(30.5,46.88) 29.71,46.88 v1(29.69,46.9)
  TOP w0.203: v1(49.52,45.22) 49.12,44.82 U3.AF11 ; v1(50.69,42.4) 50.63,42.34 U3.AF8 ; M1.G10 v1(26.58,76.95) ; v1(49.7,39.55) 49.4,39.85 U3.AF5 ; v1(56.38,66.77) 56.06,67.09 C8.2 ; R605.2 v1(51,34.88) ; U3.B11 29.5,44.82 29.9,45.22 v1(30.49,45.22) ; C922.2 70.9,68.1 v1(70.73,67.93) ; U3.AE11 48.29,44.82 v1(48.69,45.22)
  TOP w0.25: v1(54.76,82.05) 54.76,83.03 v1(54.76,83.04) 54.76,83.64 v1(54.67,83.73)
  TOP w0.254: v1(27.6,43.83) 25.31,41.55 25.31,34.17 23.53,32.39 23.53,31.77 23.33,31.57 v1(23.18,31.57) ; C864.2 23.94,35.06 v1(24.04,35.16) 24.42,35.54 24.42,42.35 v1(26.5,44.43)
  TOP w0.3: U3.AF17 49.48,50.18 v3(49.52,50.18) ; U3.AD15 47.88,47.74 ; v1(49.48,52.66) U3.AF20
  TOP w0.305: C24.1 48.44,33.74 v1(48.11,33.41) ; v1(50.46,79.37) M2.H1 M2.H2 ; v1(26.14,29.65) 26.14,29.64 R570.1 ; C1.2 59.91,70.58 v1(60.26,70.94) ; v1(34.34,75.03) 34.02,75.35 v1(33.75,75.35) M1.E1 33.18,75.36 v1(32.79,75.75) ; GCN9.4 v1(9.44,79.21) ; v1(32.81,72.56) M1.A1 ; C541.2 26.94,66.26 v1(27.19,66.51) ; M2.K14 v1(62,77.75) ; v1(17.91,32.3) 17.62,32.01 C20.1 ; v1(46.22,56) U3.AB24 v1(45.38,55.99) ; U3.AB11 45.84,44.83 v1(45.44,45.23) ; M1.K2 M1.K1 ; M2.A14 v1(61.88,85.38) ; v1(32.94,85.53) M1.V1 v1(34.03,85.43) ; v1(29.57,80.59) M1.M5 v1(30.4,81.36) ; v1(26.56,75.88) 26.28,76.16 M1.F10 ; M2.N1 v1(50.49,75.35) ; M2.N1 v1(51.45,75.76) ; M2.N1 v1(51.45,74.95) ; M2.N3 v1(52.25,75.75) ; v1(32.81,74.14) M1.C1 v1(33.75,73.75) v1(34.34,73.75) ; C865.2 22.9,32.07 23.18,31.79 v1(23.18,31.57) 23.16,31.55 v1(20.29,31.55) ; v1(74.78,75.33) 74.68,75.43 C931.2 ; M1.A3 v1(32.05,71.72) ; C683.2 63.35,72.16 v1(62,72.16) M2.V14 v1(61.07,71.74) ; v1(21.56,30.74) 21.67,30.63 R391.1 ; v1(61.97,79.75) M2.H14 v1(61.05,78.96) ; M2.E14 v1(61.05,82.15) ; M2.E14 v1(61.94,82.15) ; M2.E14 v1(61.05,81.34) ; Q75.2 64.74,57.3 65.07,57.64 v1(65.3,57.64) ; v1(30.39,84.56) M1.T5 ; M1.T5 v1(30.4,83.75) M1.R4 ; M1.T5 v1(29.58,84.56) 29.41,84.73 29.41,85.31 v1(29.58,85.47) ; Q76.2 v1(72.52,80.24) ; v1(30.88,85.68) 31.6,84.96 M1.V3 31.75,85.11 v1(31.75,85.7) ; v1(60.25,78.96) M2.H13 v1(61.05,79.75) ; v1(52.24,83.74) M2.C3 v1(53.04,82.96) M2.C4 ; v1(22.23,79.37) M1.K14 M1.K13 v1(24.01,78.95) ; v1(61.89,83.77) M2.C14 v1(61.06,83.76) ; v1(54.78,77.17) M2.L5 v1(53.85,77.35) ; M1.H2 v1(32,78.14) ; M2.C13 60.64,83.36 v1(60.24,82.96) M2.C12 ; R23.1 v1(66.13,81.71) ; v1(53.85,75.75) M2.M5 v1(54.67,76.52) ; R566.1 26.16,27.29 v1(26.02,27.15) ; C637.2 51.18,86.3 50.77,85.89 v1(50.77,85.46) M2.A1 ; Q7.2 v1(13.77,85.26) ; M2.R3 v1(53.05,74.15) M2.R4 ; M2.M10 v1(57.84,75.76) ; R240.1 34.42,77.75 v1(33.78,77.75) M1.H1 ; M1.C12 v1(24,74.15) 23.61,73.75 M1.C13 ; v1(61.05,73.35) M2.R14 v1(62,73.75) ; M2.K1 v1(50.49,77.75) ; M2.V3 v1(53.04,72.56) ; M2.V3 52.24,72.55 v1(52.24,72.55) ; M2.V3 v1(53.03,71.73) ; C18.2 v1(32.04,23.38) ; M2.E12 v1(60.24,82.14) ; M2.E3 v1(53.05,81.36) ; v1(20.29,31.55) 19.66,31.55 19.16,32.05 19.16,35.63 v1(19.46,35.92) 21.37,35.92 21.78,35.52 X6.4 21.99,35.06 C864.2 ; v1(20.29,31.55) 20.18,31.67 X6.2 ; C539.2 26.43,71.07 v1(26.43,71.51) 26.49,71.57 26.49,72.46 M1.B10 26,72.96 26.49,73.45 26.49,74.06 M1.D10 v1(25.59,74.15) M1.C11 ; v1(53.85,72.54) M2.T5 v1(54.67,72.55) ; Q72.2 v1(9.64,86.6) ; R556.1 31.64,34.19 31.12,34.71 v1(30.85,34.71) ; M2.V12 v1(59.45,72.55) ; M2.V12 v1(60.22,71.67) ; M2.V12 v1(60.26,72.55) ; v1(62,75.35) M2.N14 v1(61.06,75.76) ; v1(60.24,85.35) M2.A12 ; M2.A12 v1(59.46,84.56) ; M2.A12 v1(60.25,84.55) ; v1(41.86,58.29) 41.86,57.4 U3.U26 ; M1.E12 v1(24,74.97) ; M1.C14 v1(22.36,73.34) ; M2.C11 v1(58.65,82.96) ; v1(21.63,83.36) v1(22.22,83.36) M1.R14 ; v1(31.2,82.15) M1.N3 v1(31.99,81.36) ; M1.R12 v1(23.99,82.96) ; v1(57.83,72.56) M2.T10 v1(57.83,73.37) ; U3.Y26 v1(43.73,56.82) ; v1(23.42,85.54) 22.84,84.96 M1.V14 v1(22.24,84.96) ; v1(53.86,84.56) M2.B5 v1(54.67,83.73) ; v1(22.32,74.93) M1.E14 v1(23.2,75.77) ; U3.P26 v1(38.76,56.8) ; M1.R4 v1(31.19,82.96) M1.R3 v1(31.2,83.76) M1.R4 ; M1.C3 v1(31.2,73.35) M1.C4 ; M2.R11 v1(58.65,74.16) M2.P10 v1(57.86,74.17) ; v1(60.24,74.96) M2.N12 v1(60.24,75.75) ; M1.F5 M1.G5 29.92,76.88 v1(29.45,76.88) ; U2.5 24.52,25.82 v1(25.21,26.51) ; U3.E22 v1(32.11,53.52) ; U3.AC8 v1(46.16,41.86) U3.AB7 45.69,41.36 45.1,41.38 U3.AA7 ; M2.K2 v1(52.24,78.16) ; v1(31.99,74.95) M1.E3 v1(31.2,75.75) ; C17.2 v1(68.99,91.53) ; GCN9.E1 v1(9.36,80.51) ; v1(51.44,82.97) M2.C1 v1(50.49,83.35) v1(49.91,83.36) ; v1(66.19,84.52) 66.45,84.27 U1.1 ; Q70.2 v1(74.15,45.76) ; v1(72.69,70.96) 72.35,71.31 R748.2 ; v1(32.31,30.73) R532.1 R528.1 ; R392.2 v1(21.33,29.72) ; M2.A3 v1(52.2,85.39) ; v1(50.48,72.14) M2.V1 v1(51.45,71.68) ; M2.K13 v1(60.24,78.16) ; GCN9.E2 v1(8.1,76.05) ; v1(24.79,85.34) M1.V12 v1(24.8,84.56) ; v1(49.91,77.75) 49.68,77.52 R241.1 ; M2.F10 v1(57.67,80.98) ; U3.AC26 v1(46.21,56.8) ; M2.R12 v1(60.25,74.15) ; v1(57.82,84.55) M2.B10 ; M1.B5 v1(29.57,73.38) ; C929.2 v1(70.35,77.1)
  TOP w0.32: M1.T10 26.56,84.16 v1(26.57,84.16) 26.57,83.06 v1(26.48,82.98)
  TOP w0.35: M1.F5 30,76.14 30.39,75.75 v1(30.39,75.75) ; U3.AB20 45.84,52.26 v1(46.25,51.85) ; U3.A2 v1(28.89,37.8) ; U3.L25 36.68,56.4 v1(36.28,56.8) ; v1(24.78,72.55) M1.A12 ; v1(53.86,81.36) 53.86,81.36 54.25,80.97 M2.F5 54.79,80.42 54.79,80.36 v1(54.78,80.31) ; M2.B10 57.67,83.57 57.67,83.14 M2.D10 ; U3.AC2 46.66,37.4 v1(47.06,37.8) ; v1(31.33,56.8) 31.35,56.78 U3.E25 ; M1.H13 23.6,77.75 v1(24,78.15) ; U3.H23 v1(33.81,54.43) ; U3.E20 v1(31.28,51.86) ; U3.P23 39.18,54.8 v1(39.6,54.37) ; v1(33.8,56.8) 34.2,56.4 U3.H25 ; U3.L23 36.7,54.8 v1(36.3,54.4) ; M1.L5 30,80.16 v1(29.57,80.59) ; M1.K1 v1(33.75,79.35) ; v1(50.49,81.75) M2.E1
  TOP w0.4: v1(29.68,58.42) 29.28,58 U3.B27 v1(28.88,57.61) ; U3.V15 43.48,48.6 v1(43.48,48.8) ; v1(44.34,36.1) 44.33,37.18 U3.Y2 ; v1(41.47,48.8) 41.24,48.3 U3.T15 ; U3.N16 38.67,48.81 v1(38.69,48.82) 38.86,48.62 U3.P15 ; v1(23.2,82.15) 23.19,82.15 M1.N14 ; v1(43.73,55.19) 44.12,54.8 U3.Y23 ; U3.E14 31.68,47.35 v1(31.3,47.74) ; v1(29.69,46.9) 29.29,47.3 U3.B14 ; U3.AB17 45.86,49.78 v1(46.27,50.19) ; U3.P15 38.74,47.85 v1(38.76,47.89) 38.23,47.3 U3.N14 ; U3.P15 39.55,47.93 v1(39.68,47.93) 40.18,47.34 U3.R14 ; U3.P15 39.18,48.38 v1(39.65,48.82) 40.18,49.28 U3.R16 ; v3(49.47,54.33) 49.47,54.36 U3.AF23 ; v1(31.33,37.8) 31.72,37.4 U3.E2 ; v1(60.24,85.35) 60.24,85.46 59.73,85.97 59.19,85.97 v1(58.66,85.44) ; U3.L5 36.76,39.8 v1(37.16,39.4) ; v3(47.88,53.5) U3.AD21 47.88,52.7 v3(47.88,52.67) 48.28,52.27 U3.AE20 ; v1(24,82.15) 24.4,81.76 M1.N12 24.4,81.75 v1(24,81.36) ; v1(37.64,51.65) 37.85,51.44 37.9,51.44 38.04,51.3 U3.N18 ; v1(54.78,80.31) 54.62,80.16 M2.G5 54.25,80.17 v1(53.86,80.56) ; U3.L12 36.18,45.37 36.63,45.82 v1(36.86,45.82) 36.86,45.97 U3.M13 ; U3.R12 40.18,45.28 v1(39.71,44.83) 39.71,44.82 U3.P11 ; v1(34.91,43.79) 35.2,44.3 U3.K11 ; v1(32.11,50.2) 31.69,49.78 U3.E17 ; U3.AB14 46.27,47.72 v1(46.27,47.73) ; U3.AG2 49.88,37.32 v1(49.53,36.97) ; U3.B20 v1(28.85,51.89) ; U3.K13 35.23,46.3 v1(34.75,45.71) ; U3.L16 36.18,49.3 v1(36.68,49.58) 37.18,50.02 U3.M17 ; U3.N12 38.18,45.31 v1(38.66,45.73) 39.17,46.3 U3.P13 ; v1(29.67,41.92) 29.28,42.3 U3.B8 ; U3.T17 41.57,50.68 v1(41.57,50.72) 42.18,51.27 U3.U18 ; v1(42.08,54.38) 41.67,54.8 U3.U23 ; U3.U14 41.7,46.81 v1(41.67,46.81) 41.67,46.79 U3.T13 41.72,45.76 v1(41.79,45.76) 42.18,45.37 U3.U12 ; v1(40.38,51.94) 40.18,51.74 U3.R18 ; U3.L14 36.19,47.3 v1(36.7,47.74) 37.18,48.22 U3.M15 ; U3.L18 36.21,51.3 v1(36.64,51.82) ; v1(34.92,50.8) 35.18,50.53 U3.K17 ; v1(40.16,42.22) 40.18,42.24 U3.R10 ; U3.K15 35.18,48.2 v1(34.91,47.79) ; 47.88,47.74 v3(47.88,47.71) 48.28,47.31 U3.AE14 48.29,47.3 v1(48.69,47.7) 49.08,47.3 U3.AF14 ; v1(38.69,50.58) 38.9,50.58 U3.P17 ; M1.H14 22.8,77.75 v1(23.19,77.36) 23.2,77.36 M1.H13 ; v1(38.18,42.22) U3.N10 ; M2.G10 v1(57.66,80.16) ; U3.B23 29.28,54.8 v1(28.88,55.21) ; U3.U10 41.73,43.85 v1(41.67,43.85) 41.22,44.3 U3.T11 ; v1(43.49,44.83) 43.49,44.61 U3.V11 ; v1(43.49,46.78) 43.18,46.47 U3.V13 ; U3.B1 29.28,36.4 v1(28.97,36.09) ; M1.R1 v1(33.75,83.35) ; M2.E1 v1(51.45,81.36) ; M2.R1 v1(50.49,73.75) 49.9,73.78 v1(49.9,73.78) ; v1(53.84,85.35) 53.84,86.06 53.23,86.67 C629.2 52.99,86.67 52.2,85.88 v1(52.2,85.39) ; U3.U16 v1(42.7,49.81) U3.V17 ; v1(29.7,49.37) 29.69,49.37 U3.B17 v1(28.88,49.38) ; v1(50.49,81.75) 49.91,81.75 49.91,81.76
  TOP w0.406: v1(22.29,77.33) 21.79,76.83 C575.2 ; v1(22.29,77.33) M1.H14 ; v1(22.29,77.33) 21.94,77.68 C542.2 21.04,77.68 R180.1 ; M1.N1 v1(33.75,81.75) ; v1(30.88,85.68) 30.88,86.62 C631.2 31.75,86.29 v1(31.75,85.7) ; v1(29.7,39.44) 29.29,39.85 U3.B5 ; v1(22.32,74.93) 21.1,74.93 C576.2 ; U3.AC22 46.68,53.9 v1(46.26,53.48) ; U3.AD18 v3(47.88,51.01) U3.AD19 ; C3.2 62.05,79.83 v1(61.97,79.75) ; C560.2 24.17,86.86 C633.2 v1(23.15,87.71) ; M1.A14 22.79,72.16 v1(22.36,71.73) 22.3,71.67 v1(21.49,71.67) 21.14,71.33 C543.2 ; v1(26.57,84.16) 27.09,84.69 C540.2 ; U3.AD16 v3(47.87,49.35) U3.AE17 ; U3.Y5 44.14,39.8 v1(43.79,39.45) ; U3.L10 v1(36.69,43.8) U3.M11 ; U3.E8 31.68,42.33 v1(31.29,41.94) ; v1(33.75,83.35) 34.5,83.35 C622.2 ; M1.M10 v1(26.44,80.57) M1.L10 ; U3.AF1 v1(49.44,36.24) ; U3.A26 28.48,57.21 v1(28.88,57.61) ; 49.91,81.76 49.74,81.93 C748.1 ; v1(26.48,82.98) M1.P10 v1(25.6,82.95) M1.R11 ; M1.N14 v1(22.24,81.75) 21.92,82.08 C578.2 ; C681.2 59.06,87.17 v1(59.58,87.69) ; C630.1 49.87,83.33 v1(49.91,83.36) ; v1(22.23,79.37) 22.04,79.56 R181.1 ; v1(62,77.75) 62.69,77.06 R4.1 ; U3.E11 v1(31.3,44.41) ; v1(61.94,82.15) 62.24,82.44 C682.2 ; v1(50.28,56.81) 49.89,57.2 U3.AG26 ; v1(46.2,39.43) 46.62,39.85 U3.AC5 ; U3.AD22 47.48,53.89 v3(47.88,53.5) ; C867.1 36.21,8.3 v1(36.06,8.15) GR13.2 ; v1(58.65,77.35) 58.25,76.96 M2.L10 ; C596.2 21.16,83.84 v1(21.63,83.36) 22.21,83.36 v1(22.22,83.36) 22.79,83.36 M1.R14 ; C623.1 50.03,71.69 v1(50.48,72.14) ; C606.2 34.39,85.8 v1(34.03,85.43) ; Q71.2 v1(54.49,52.89) ; U3.E5 v1(32.13,39.46) ; U3.AD13 U3.AD12 47.48,45.6 v1(47.86,45.22) ; R661.1 v1(71.86,19.98)
  TOP w0.508: v1(41.11,3) 41.25,2.86 GCN1.40 ; v1(36.61,4.29) 36.84,4.29 37.25,3.88 GCN1.50 ; GCN1.34 43.65,2.72 43.39,2.98 v1(43.29,2.98)
  BOTTOM w0.203: v1(58.57,68.74) 58.85,69.02 C5.2
  BOTTOM w0.25: M2.K1 51.16,77.64 51.73,77.64 ; v1(54.76,82.05) 54.85,82.14 54.85,82.94 v1(54.76,83.04) 54.76,83.64 v1(54.67,83.73)
  BOTTOM w0.254: GU1.22 62.45,38.61 v1(62.79,38.95) ; U39.5 60.41,52.55 U39.E1 ; M2.K2 51.73,77.64
  BOTTOM w0.305: v1(13.16,72.62) 13.2,72.66 GQ2.2 ; M2.R4 v1(53.05,74.15) M2.R3 ; R648.1 v1(65.4,43.42) ; R19.1 R5.1 v1(55.39,87.51) ; R10.1 R187.1 v1(27.67,88.2) ; C742.2 62.24,85.73 v1(61.88,85.38) M2.A14 ; R247.1 27.3,58.11 v1(27.71,57.7) ; C900.1 11.98,39.33 v1(11.84,39.48) ; C692.2 62.9,73.75 v1(62,73.75) M2.R14 v1(61.05,73.35) ; v1(53.85,72.54) M2.T5 v1(54.67,72.55) ; v1(58.66,85.44) 58.57,85.53 C561.2 ; M2.R11 v1(58.65,74.16) M2.P10 v1(57.86,74.17) ; M2.V3 v1(53.04,72.56) ; M2.V3 v1(52.24,72.55) ; M2.V3 v1(53.03,71.73) ; v1(61.89,83.77) M2.C14 v1(61.06,83.76) ; M1.E1 33.18,75.36 v1(32.79,75.75) ; M2.G10 M2.F10 57.69,80.96 v1(57.67,80.98) ; R533.1 v1(32.54,31.28) ; M1.G10 M1.F10 26.54,75.87 26.56,75.88 v1(26.56,75.88) ; C879.1 67.58,39.18 68.43,40.02 v1(68.43,40.15) ; U38.5 67.56,60.66 U38.E1 ; M1.H2 v1(32,78.14) ; v1(61.07,71.74) M2.V14 v1(62,72.16) 62.02,72.18 ; v1(25.67,14.85) 25.86,15.04 U41.3 ; R738.2 69.08,66.27 v1(69.1,66.29) ; GR9.2 v1(66.29,33.68) ; C918.2 62.09,49.63 v1(62.55,50.08) ; v1(28.89,37.8) 28.74,37.95 R198.1 ; v1(68.17,31.59) C891.2 R664.2 ; v1(47.06,37.8) 47.28,38.02 C536.2 ; U43.3 v1(24.76,12.86) ; GC316.2 v1(12.96,76.68) ; C930.2 v1(28.47,13.95) ; M1.L5 v1(29.57,80.59) M1.M5 v1(30.4,81.36) ; GC315.1 v1(14.28,71.6) ; Q25.2 v1(29.58,22.81) ; M1.R4 v1(31.19,82.96) M1.R3 v1(31.2,83.76) M1.R4 ; M1.R4 v1(30.4,83.75) M1.T5 ; C875.2 57.72,38.46 v1(57.8,38.54) 57.94,38.68 C874.2 ; v1(57.83,73.37) M2.T10 v1(57.83,72.56) ; v1(10.59,33.76) 10.59,33.76 U37.7 ; v1(23.25,15.03) 23.11,15.17 C928.2 C927.2 ; M2.L5 v1(53.85,77.35) ; M2.L5 v1(54.78,77.17) ; M2.L5 v1(54.67,76.52) ; M2.V12 v1(60.22,71.67) ; M2.V12 v1(59.45,72.55) ; M2.V12 v1(60.26,72.55) ; v2(70.69,33.99) 70.5,34.18 R665.2 ; v1(60.24,74.96) M2.N12 v1(60.24,75.75) ; M2.N14 v1(61.06,75.76) ; v1(66.1,31.4) 65.79,31.09 GC3.1 ; GC317.1 v1(9.95,74.47) ; M1.H1 v1(33.78,77.75) ; v1(13.64,14.31) 13.64,14.3 C863.2 ; R699.2 12.97,40.04 v1(12.69,40.33) ; v1(31.99,81.36) M1.N3 v1(31.2,82.15) ; v1(27.6,43.83) 28.07,44.31 R587.1 ; v1(29.28,28.16) Q30.2 30.03,28.54 30.59,29.1 R604.1 ; M2.F5 v1(53.86,80.56) M2.G5 v1(54.78,80.31) ; M1.B5 v1(29.57,73.38) ; R248.1 28.75,59.22 v1(28.9,59.08) ; R703.2 10.65,28.88 v1(10.73,28.81) ; C932.2 v1(8.57,22.24) ; v1(33.85,18.13) 34.15,17.82 Q2.2 ; M2.C11 v1(58.65,82.96) M2.D10 ; C878.1 v1(65.43,44.19) ; M1.T5 v1(29.58,84.56) ; M1.T5 v1(30.39,84.56) ; R595.1 17.87,12.87 v1(17.68,12.68) 17.49,12.87 R597.1 ; GC2.1 67.95,37.71 67.72,37.47 v1(67.64,37.47) ; v1(64.02,45.34) 64.02,45.67 64.3,45.95 R744.1 ; U46.3 v1(10.44,27.15) ; C620.2 38.96,53.73 v1(39.6,54.37) ; v1(29.45,76.88) 29.57,76.88 29.64,76.96 M1.G5 ; C537.2 48.79,36.89 v1(49.44,36.24) ; C917.2 67.19,64.47 66.94,64.23 v1(66.94,64.05) ; M2.N1 v1(51.45,75.76) ; M2.N1 v1(51.45,74.95) ; M2.N1 v1(50.49,75.35) ; M1.B10 v1(26.53,72.96) ; M2.A3 v1(52.2,85.39) ; v1(65.75,58.17) 66.73,58.17 C913.1 ; M1.C14 v1(22.36,73.34) ; R596.1 v1(15.73,25.59) ; M2.K14 v1(62,77.75) ; v1(61.13,65) 61.32,65.2 Q55.2 ; M4.C13 60.65,73.76 v1(60.25,74.15) M2.R12 ; Q4.2 35.93,13.69 v1(35.47,14.15) ; C22.1 39.1,15.18 R40.2 v1(39.7,15.17) ; C588.2 51.23,86.28 50.77,85.83 v1(50.77,85.46) 50.77,85.23 M2.A1 51.05,84.94 v1(51.43,84.56) ; C915.1 v1(60.59,51.24) ; GC1.2 70.42,36.16 v1(70.42,36.16) ; C23.1 v1(36.65,16.13) ; C933.2 v1(10.44,21.84) ; U37.8 v1(10.56,35.26) ; M1.N1 v1(33.75,81.75) ; v1(31.99,74.95) M1.E3 ; U4.3 v1(36.88,10.23) ; M2.C4 v1(53.04,82.96) M2.C3 v1(52.24,83.74) ; U44.3 v1(24.98,10.96) ; R44.2 v1(38.88,17.73) ; M2.L10 v1(58.65,77.35) ; U36.4 v1(18.27,23.7) ; M2.B10 v1(57.82,84.55) ; C910.1 v1(12.99,29.2) ; v1(26.43,71.51) 26.36,71.44 C4.2 ; C21.1 v1(32.8,12.63) ; M2.E12 v1(60.24,82.14) ; M2.C12 v1(60.24,82.96) ; C851.2 v1(33.2,27.51) ; C916.1 v1(68.81,61.34) ; R32.2 v1(32.8,10.14) ; v1(52.24,78.16) M2.K2 ; C888.2 v1(66.03,44.27) ; M1.F5 v1(30.39,75.75) ; M1.E12 v1(24,74.97) ; C852.2 v1(32.62,28.55)
  BOTTOM w0.32: v1(54.67,83.73) 54.24,84.16 M2.B5
  BOTTOM w0.35: M2.F5 54.25,80.97 v1(53.86,81.36) ; v1(50.49,73.75) M2.R1 ; M1.C4 30.8,73.75 v1(31.2,73.35) 31.6,73.75 M1.C3 ; M1.D10 26,74.55 v1(25.59,74.15) 25.2,73.75 M1.C11 ; v1(50.49,81.75) M2.E1 ; v1(53.85,75.75) M2.M5 54.25,76.16 54.61,76.52 v1(54.67,76.52) ; M1.E3 31.59,75.35 v1(31.2,75.75) ; v1(24.78,72.55) M1.A12 ; M1.R1 v1(33.75,83.35) ; v1(22.36,71.73) 22.55,71.97 22.55,71.98 22.62,71.98 M1.A14 ; M2.E3 52.65,81.75 v1(53.05,81.36)
  BOTTOM w0.4: v3(47.88,53.5) 47.87,53.49 C276.2 ; v1(49.91,77.75) 50.49,77.75 v1(50.49,77.75) M2.K1 ; v1(26.48,82.98) 26.42,82.98 M1.P10 ; v1(22.22,83.36) 22.21,83.36 v1(21.63,83.36) ; 50.28,75.57 v1(50.49,75.35) ; M1.C3 31.6,73.75 v1(32,73.37) ; v1(24,82.15) 24.4,81.76 M1.N12 v1(24,81.36) ; v1(38.79,39.42) C866.2 39.81,39.11 C858.2 ; v1(51.45,71.68) 51.05,72.09 M2.V1 50.5,72.16 v1(50.48,72.14) 49.89,71.55 ; v1(24,78.15) 23.6,77.75 M1.H13 23.59,77.75 v1(23.19,77.36) 23.19,77.36 M1.H14 22.72,77.75 v1(22.29,77.33) 22.27,77.35 ; v1(33.75,75.35) 34.02,75.35 v1(34.34,75.03) ; C474.2 46.43,52.03 v1(46.25,51.85) ; M2.N14 v1(62,75.35) 62,75.35 62.58,75.35 ; v1(23.2,82.15) 23.19,82.15 M1.N14 v1(22.24,81.75) ; v1(32.05,71.72) 32.03,71.72 M1.A3 ; v1(57.84,75.76) 57.85,75.76 M2.M10 ; M2.E14 61.44,81.75 v1(61.05,82.15) ; M2.E14 61.05,81.35 v1(61.05,81.34) ; M2.E14 61.5,81.75 v1(61.94,82.15) ; v1(40.43,53.56) 40.41,53.56 v1(39.6,54.37) 40.42,55.19 v1(40.42,55.19) ; v1(46.22,56) 46.22,56.79 v1(46.21,56.8) ; v1(26.44,80.57) 26.02,80.16 M1.L10 ; 49.53,54.26 v3(49.47,54.33) ; v1(49.9,73.78) 49.92,73.75 v1(50.49,73.75) ; M1.C12 v1(24,74.15) ; M2.B5 54.25,84.16 v1(53.86,84.56) ; v1(31.75,85.7) 31.77,85.13 M1.V3 31.6,85 v1(30.88,85.68) ; M1.T10 26.56,84.16 v1(26.57,84.16) 26.57,85.54 ; 21.55,71.73 v1(22.36,71.73) ; v1(50.28,56.81) 50.33,56.76 R171.1 ; M2.E1 v1(51.45,81.36) ; v1(34.34,73.75) v1(33.75,73.75)
  BOTTOM w0.406: v1(33.75,81.75) 33.77,81.73 C572.2 ; 49.89,71.55 49.5,71.16 C745.2 ; C370.2 45.63,48.36 v1(46.27,47.73) ; C859.2 38.08,42.12 v1(38.18,42.22) 38.67,42.71 C820.2 ; M1.R14 v1(22.22,83.36) ; v1(32.81,74.14) M1.C1 v1(33.75,73.75) ; C276.2 46.27,53.49 v1(46.26,53.48) 46.21,53.43 C14.2 46.21,51.89 v1(46.25,51.85) ; v1(31.75,85.7) 31.75,86.15 C605.2 30.88,86.53 v1(30.88,85.68) ; M1.E14 22.81,75.36 v1(23.2,74.96) ; M1.E14 v1(22.32,74.93) 22.31,74.92 C557.2 ; M1.E14 22.8,75.37 v1(23.2,75.77) ; C338.2 46.1,50.36 v1(46.27,50.19) ; 49.53,54.26 49.61,54.19 C568.2 ; R7.1 48.88,79.3 C599.2 49.54,79.37 v1(50.46,79.37) 50.47,79.36 M2.H1 M2.H2 ; v1(44.34,36.1) 44.62,35.82 C831.2 ; v1(22.23,79.37) M1.K14 M1.K13 v1(24.01,78.95) ; M2.A12 v1(60.24,85.35) ; M2.A12 v1(59.46,84.56) ; M2.A12 v1(60.25,84.55) ; v1(50.49,81.75) 50.21,82.04 C579.2 ; v1(22.24,84.95) M1.V14 v1(23.42,85.54) ; M1.M10 v1(26.44,80.57) ; M1.R11 v1(25.6,82.95) M1.P10 ; 26.57,85.54 25.83,86.28 C559.2 ; v1(22.24,81.75) 22.02,81.53 C554.2 ; v1(46.2,39.43) 46.2,39.43 R606.2 ; v1(33.75,79.36) M1.K1 M1.K2 ; 34.97,75.3 C584.2 34.61,75.3 v1(34.34,75.03) ; R18.1 62.75,77 v1(62,77.75) ; v1(32.81,72.56) 33.2,72.17 M1.A1 ; M2.H13 v1(61.05,79.75) M2.H14 ; M2.H13 v1(61.05,78.96) M2.H14 ; M2.H13 v1(60.25,78.96) ; 62.58,75.35 62.74,75.2 C562.2 ; v1(32.54,31.28) 32.74,31.08 C857.2 ; 21.55,71.73 v1(21.49,71.67) 21.07,71.25 C636.2 ; M3.C13 23.6,83.35 v1(23.99,82.96) M1.R12 ; M2.H14 v1(61.97,79.75) 63.17,79.75 C9.2 ; v1(49.9,73.78) 49.89,73.79 C581.2 ; C684.2 59.93,87.33 v1(59.58,87.69) ; v1(61.94,82.15) 62.23,82.44 C741.2 ; v1(33.47,71.65) 33.51,71.69 C558.2 ; R9.1 20.18,78.29 C6.2 20.18,77.48 20.52,77.15 C556.2 21.01,77.33 v1(22.29,77.33) ; C583.2 34.63,73.46 v1(34.34,73.75) ; M2.K13 60.64,77.75 v1(60.24,78.16) ; R688.2 17.5,32.3 v1(17.91,32.3) 17.91,33.17 C899.2 ; 47.24,52.03 v3(47.88,52.67) ; 47.24,52.03 47.44,52.03 47.88,51.59 v3(47.88,51.01) ; 47.24,52.03 C474.2 ; M1.E1 v1(33.75,75.36) ; R1722.1 34.48,77.75 v1(33.78,77.75) ; v1(21.63,83.36) 21.63,83.36 C555.2 ; v1(32.94,85.53) M1.V1 v1(32.79,84.56) ; v1(24.8,84.56) M1.V12 v1(24.79,85.34) ; v1(46.21,56.8) 46.09,56.8 45.73,57.16 C275.2 ; M2.N3 v1(52.25,75.75) ; 50.28,75.57 50.23,75.62 C580.2 ; v1(51.44,82.97) M2.C1 v1(50.49,83.35) 50.49,83.36 v1(49.91,83.36) 49.41,83.86 C597.2 ; C914.1 v1(59.25,51.15)
  BOTTOM w0.508: GCN1.47 v1(38.45,3.06) ; v1(46.61,3.49) 46.45,3.33 GCN1.27 ; v1(41.11,3) 40.85,2.74 GCN1.41 ; v1(57.39,36.4) 57.59,36.21 R659.2 ; GCN1.29 45.65,3.29 45.53,3.41 v1(45.53,3.42) ; GCN1.9 56.85,3.1 v1(56.6,3.35) ; v1(53.02,4.57) 54.45,3.13 GCN1.15 ; C574.2 37.08,37.87 v1(37.15,37.8) ; GCN1.21 48.85,3.12 v1(48.76,3.22) ; v1(43.29,2.98) 43.25,2.93 GCN1.35 ; R650.2 v1(57.75,39.62)
  vias: v1(7.28,97.48) v1(7.3,92.8) v1(7.3,90.26) v1(7.3,87.72) v1(7.3,85.18) v1(7.3,82.64) v1(7.3,77.56) v1(7.3,72.48) v1(7.3,69.94) v1(7.3,64.86) v1(7.3,62.32) v1(7.3,59.78) v1(7.3,57.24) v1(7.3,54.7) v1(7.3,52.16) v1(7.3,49.62) v1(7.3,47.08) v1(7.3,44.54) v1(7.3,42) v1(7.3,39.46) v1(7.3,36.92) v1(7.3,34.38) v1(7.3,31.84) v1(7.3,29.3) v1(7.3,26.76) v1(7.3,24.22) v1(7.3,21.68) v1(7.3,19.14) v1(7.3,16.6) v1(7.3,14.06) v1(7.3,11.52) v1(7.3,8.98) v1(7.3,6.44) v1(7.3,3.9) v1(9.06,18.03) v1(9.84,3.9) v1(9.94,6.65) v1(10.49,91.81) v1(12.29,35.2) v1(12.27,33.76) v1(12.27,6.41) v1(12.36,97.48) v1(12.38,3.9) v1(12.99,34.48) v1(13.03,91.81) v1(13.26,94.9) v1(13.6,35.2) v1(13.73,33.74) v1(14.9,97.48) v1(14.87,6.41) v1(14.92,3.9) v1(15.57,91.81) v1(15.8,94.9) v1(17.44,97.48) v1(17.46,3.9) v1(18.34,94.9) v1(18.55,91.88) v1(19.15,88.32) v1(19.98,97.48) v1(20,3.9) v1(21.09,91.88) v1(22.54,3.9) v1(23.63,91.88) v1(24.61,97.43) v1(25.08,3.9) v1(25.22,94.02) v1(26.01,70.13) v1(26.61,23.68) v1(26.86,51.75) v1(27.09,91.71) v1(27.11,70.1) v1(27.18,54.35) v1(27.29,95.65) v1(27.29,48.89) v1(27.48,50.74) v1(27.62,53.89) v1(27.62,3.9) v1(28.04,47.63) v1(28.14,50.17) v1(28.27,93.35) v1(30.16,3.9) v1(30.89,91.55) v1(32.7,3.9) v1(32.99,36.99) v1(32.98,36.12) v1(32.96,35.35) v1(33.43,91.55) v1(33.83,40.16) v1(34.17,45.74) v1(34.42,4.01) v1(34.43,49.7) v1(35.97,91.55) v1(36.6,25.1) v1(36.68,24.1) v1(37.71,47.81) v1(38.24,24.06) v1(38.51,91.55) v1(39.27,58.35) v1(39.46,60) v1(39.61,55.99) v1(39.62,24.08) v1(40.12,11.51) v1(40.49,92.88) v1(40.46,61.02) v1(40.44,59.71) v1(40.42,58.44) v1(40.68,50.93) v1(40.87,24.06) v1(41.05,74.3) v1(41.06,73.83) v1(41.06,73.3) v1(41.06,72.76) v1(41.41,90.89) v1(41.38,83.83) v1(41.38,83.24) v1(41.38,82.71) v1(41.38,82.17) v1(41.53,10.1) v1(41.63,95.27) v1(41.63,11.75) v1(41.85,60.74) v1(41.85,59.53) v1(42.27,24.06) v1(42.94,60.17) v1(42.94,59.57) v1(43.24,10.19) v1(43.55,49.84) v1(43.52,24.03) v1(43.83,51.53) v1(43.97,49.41) v1(43.97,47.23) v1(44.36,49.92) v1(44.6,24.71) v1(44.72,97.44) v1(45,60.08) v1(45.01,59.47) v1(46.99,25.7) v1(47.26,97.44) v1(47.46,61.98) v1(47.46,60.8) v1(47.46,59.58) v1(47.98,31.99) v1(48.09,27.42) v1(48.09,26.26) v1(48.15,30.94) v1(48.17,29.7) v1(48.14,28.6) v1(48.3,61.65) v1(48.27,60.23) v1(49.8,97.44) v1(49.85,94.56) v1(49.85,91.78) v1(51.1,53.32) v1(51.57,53.32) v1(51.69,56.94) v1(51.97,22.9) v1(51.97,21.06) v1(52.04,53.31) v1(52.27,56.95) v1(52.34,97.44) v1(52.39,94.56) v1(52.39,91.78) v1(52.53,53.31) v1(53.44,22.81) v1(53.45,20.96) v1(53.54,24.54) v1(54.88,97.44) v1(54.93,94.56) v1(54.93,91.78) v1(55.38,42.75) v1(55.37,40.98) v1(55.47,21.58) v1(55.5,19.69) v1(56.71,53.05) v1(56.69,52.56) v1(56.72,53.55) v1(56.86,56.75) v1(56.86,56.26) v1(57.25,53.76) v1(57.42,97.44) v1(57.47,94.56) v1(57.47,91.78) v1(57.86,66.66) v1(58.61,56.77) v1(58.6,56.29) v1(59.55,34.77) v1(59.86,33.17) v1(59.96,97.44) v1(60.55,91.67) v1(60.88,56.97) v1(60.9,56.48) v1(61.16,53.82) v1(61.18,52.76) v1(61.54,59.39) v1(62.01,70.94) v1(62.06,59.42) v1(63.06,87.55) v1(63.36,38.95) v1(63.35,37.85) v1(63.78,91.9) v1(63.88,38.95) v1(63.89,37.85) v1(65.04,97.44) v1(65.18,94.38) v1(65.34,59.2) v1(65.33,58.72) v1(65.41,35.66) v1(65.81,58.74) v1(65.82,59.21) v1(66,66.12) v1(66.14,75.1) v1(66.13,74.59) v1(66.29,61.55) v1(66.99,61.56) v1(67.11,75.68) v1(67.11,75.14) v1(67.12,74.63) v1(67.12,74.08) v1(67.58,97.44) v1(67.72,94.38) v1(69.07,72.97) v1(69.07,72.21) v1(70.12,97.44) v1(70.17,73.01) v1(70.17,72.25) v1(70.26,94.38) v1(70.36,65.87) v1(70.35,65.4) v1(70.45,27.13) v1(70.85,65.87) v1(70.84,65.4) v1(71.07,66.31) v1(71.34,65.87) v1(71.32,65.4) v1(71.59,66.31) v1(71.81,65.4) v1(71.82,65.87) v1(75.96,97.48) v1(75.96,92.78) v1(75.96,90.24) v1(75.96,87.7) v1(75.96,85.16) v1(75.96,82.62) v1(75.96,80.08) v1(75.96,77.54) v1(75.96,75) v1(75.96,72.46) v1(75.96,69.92) v1(75.96,67.38) v1(75.96,64.84) v1(75.96,62.3) v1(75.96,59.76) v1(75.96,57.22) v1(75.96,54.68) v1(75.96,52.14) v1(75.96,49.6) v1(75.96,47.06) v1(75.96,44.52) v1(75.96,41.98) v1(75.96,39.44) v1(75.96,36.9) v1(75.96,34.36) v1(75.96,31.82) v1(75.96,29.28) v1(75.96,26.74) v1(75.96,24.2) v1(75.96,21.66) v1(75.96,19.12) v1(75.96,16.58) v1(75.96,14.04) v1(75.96,11.5) v1(75.96,8.96) v1(75.96,6.42) v1(75.96,3.88) v2(8.31,40.98) v2(8.37,43.39) v2(8.36,42.56) v2(8.32,41.8) v2(8.47,56.2) v2(8.46,55.38) v2(8.45,54.59) v2(8.46,53.78) v2(8.71,73.4) v2(8.7,72.57) v2(8.74,71.82) v2(8.72,71) v2(9.21,54.59) v2(9.23,56.2) v2(9.22,55.38) v2(9.22,53.78) v2(9.47,73.4) v2(9.46,72.57) v2(9.5,71.82) v2(9.49,71) v2(9.97,56.25) v2(9.98,55.43) v2(10.01,54.62) v2(10.01,53.78) v2(10.05,12.5) v2(10.06,11.69) v2(10.81,12.5) v2(10.82,11.69) v2(11.61,12.53) v2(11.61,11.69) v2(17.2,63.11) v2(17.42,56.86) v2(17.88,79.2) v2(17.87,78.38) v2(17.91,77.63) v2(17.89,76.8) v2(17.96,63.1) v2(18.21,56.89) v2(25.17,60.56) v2(25.18,59.71) v2(25.21,58.91) v2(25.22,58.08) v2(57.19,21.33) v2(57.18,20.57) v2(57.95,21.35) v2(57.94,20.6) v2(68.22,30.65) v2(68.22,29.81) v2(68.22,29.03) v2(68.53,48.58) v2(68.53,47.76) v2(68.53,46.91) v2(68.53,46.06) v2(68.97,30.65) v2(68.97,29.81) v2(68.97,29.03) v2(69.34,48.58) v2(69.34,47.76) v2(69.34,46.91) v2(69.34,46.06) v2(69.72,30.65) v2(69.72,29.81) v2(69.72,29.03) v2(70.19,48.58) v2(70.19,47.76) v2(70.19,46.91) v2(70.19,46.06) v2(70.47,30.66) v2(70.47,29.83) v2(70.47,29.04) v2(70.66,34.73) v2(70.7,33.25) v2(70.74,32.52) v2(72.81,12.34) v2(72.73,9.1) v2(72.75,8.32) v2(73.61,12.34) v2(73.53,9.1) v2(73.52,8.34) v2(74.41,86.98) v2(74.41,12.32) v2(74.33,9.09) v2(74.32,8.32) v2(74.79,85.74) v2(74.75,85.01) v3(50.46,49.28) v3(51.26,62.57) v3(51.54,48.25) v3(51.88,62.56) v3(52.48,62.58) v3(53.07,62.57) v3(53.13,48.85) v3(57.07,64.52) v3(57.07,63.98) v3(58.29,64.05) v3(58.46,64.57)
